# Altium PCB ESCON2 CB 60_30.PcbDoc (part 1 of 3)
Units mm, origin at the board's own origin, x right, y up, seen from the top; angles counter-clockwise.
Board outline 93.5 x 46 mm, 8 copper layers (Top Side, Inner Layer 1, Inner Layer 2, Inner Layer 3, Inner Layer 4, Inner Layer 5, Inner Layer 6, Bottom Side), stack 1.485 mm thick; 144 components, 77 nets, 473 pads, 3049 vias.
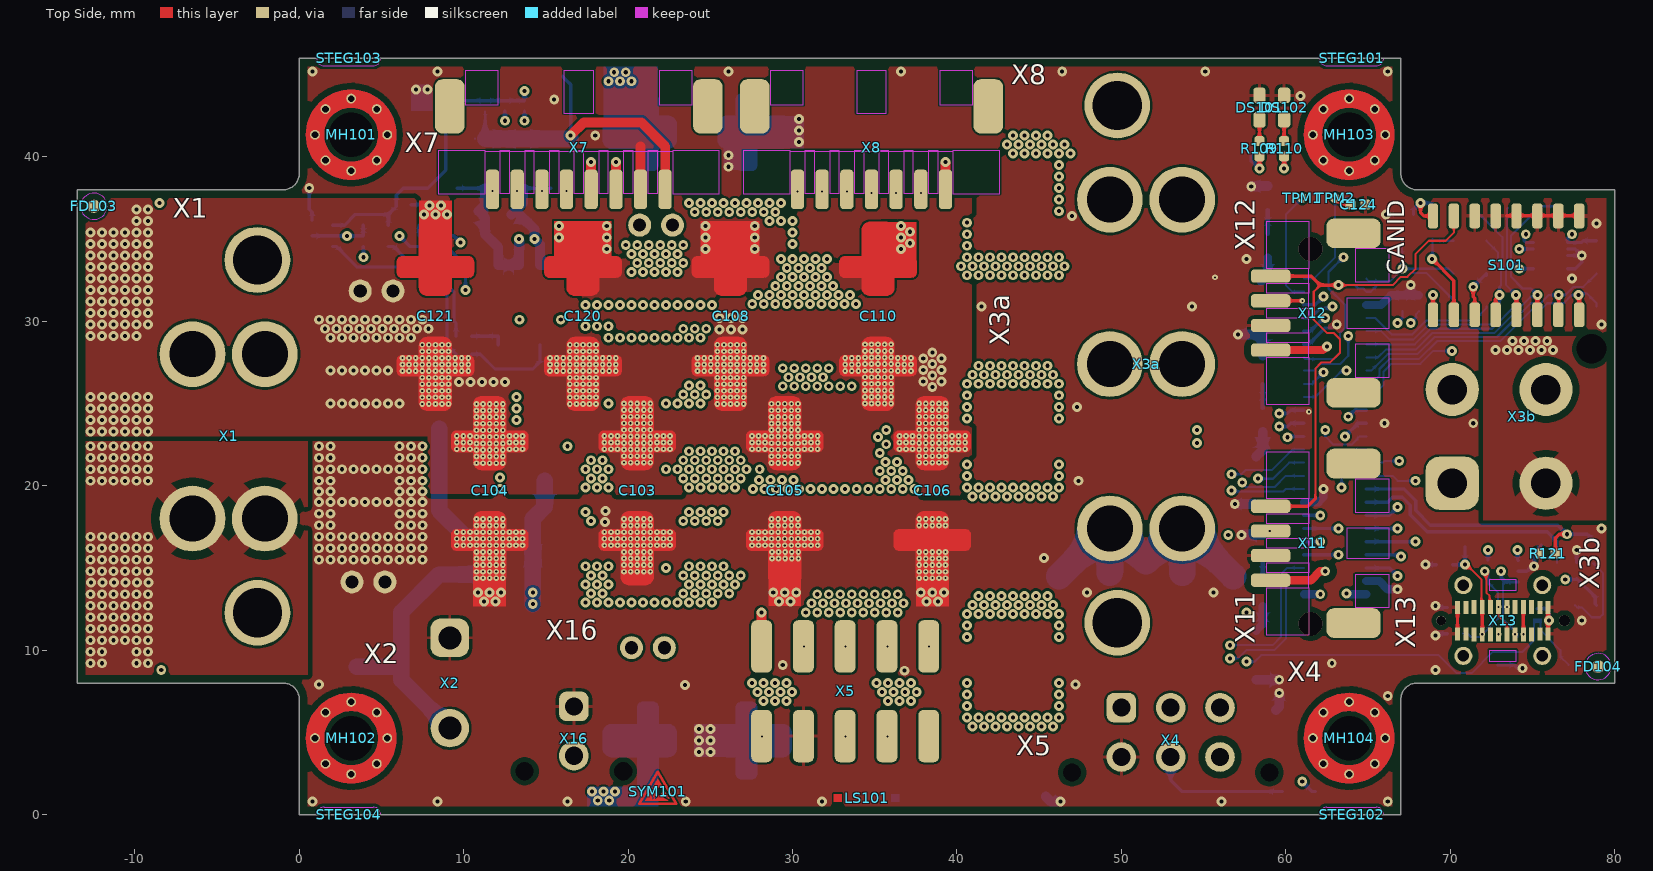
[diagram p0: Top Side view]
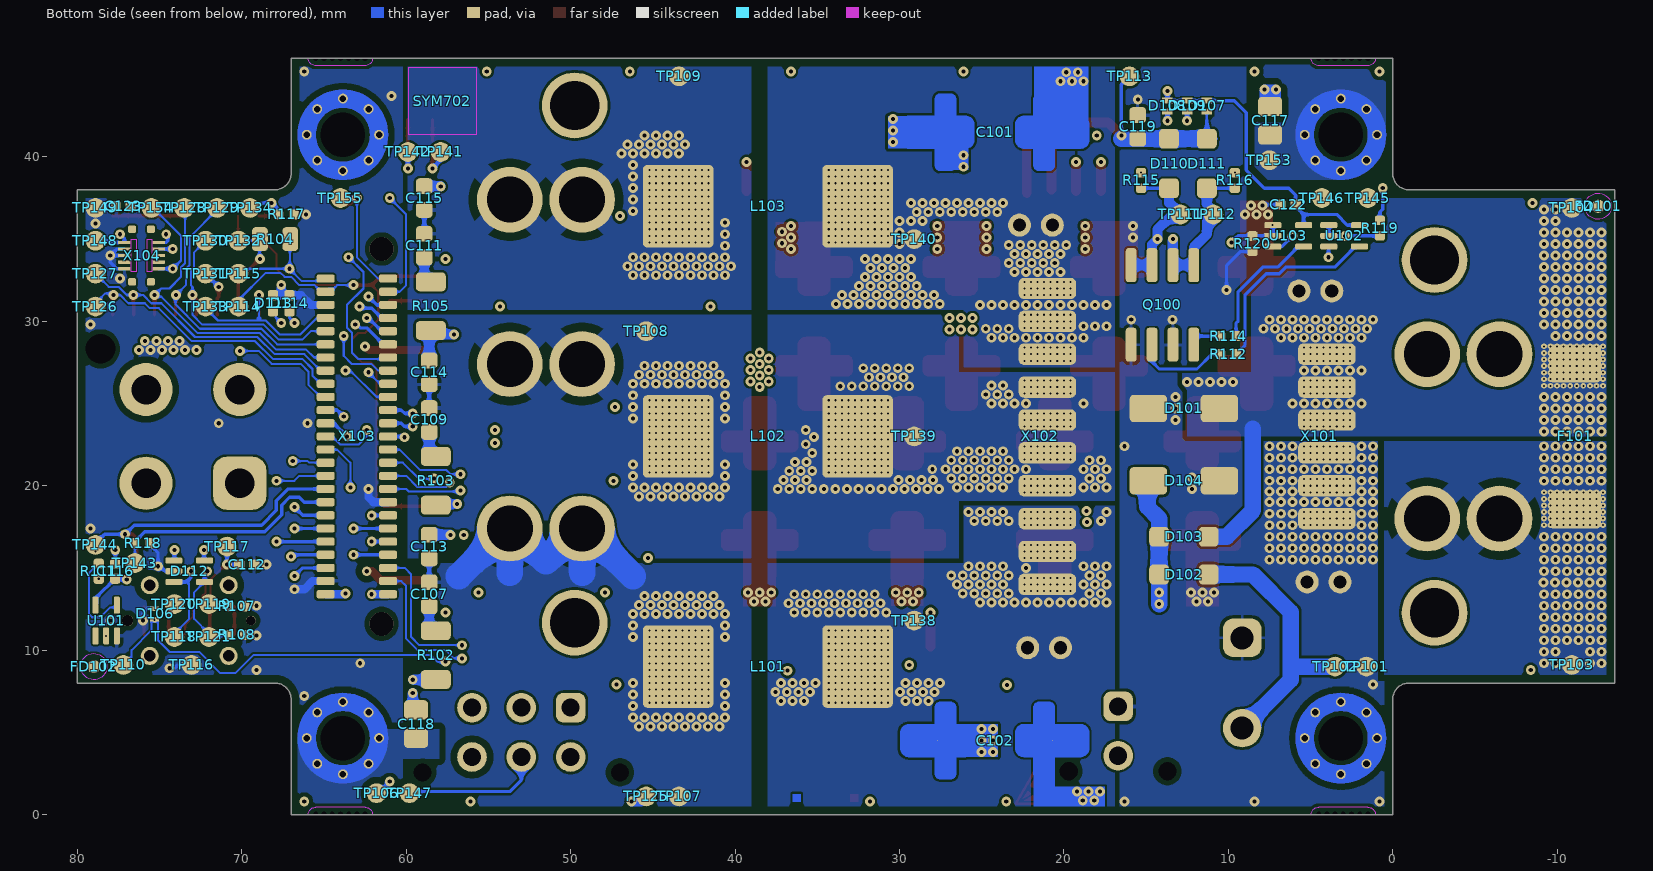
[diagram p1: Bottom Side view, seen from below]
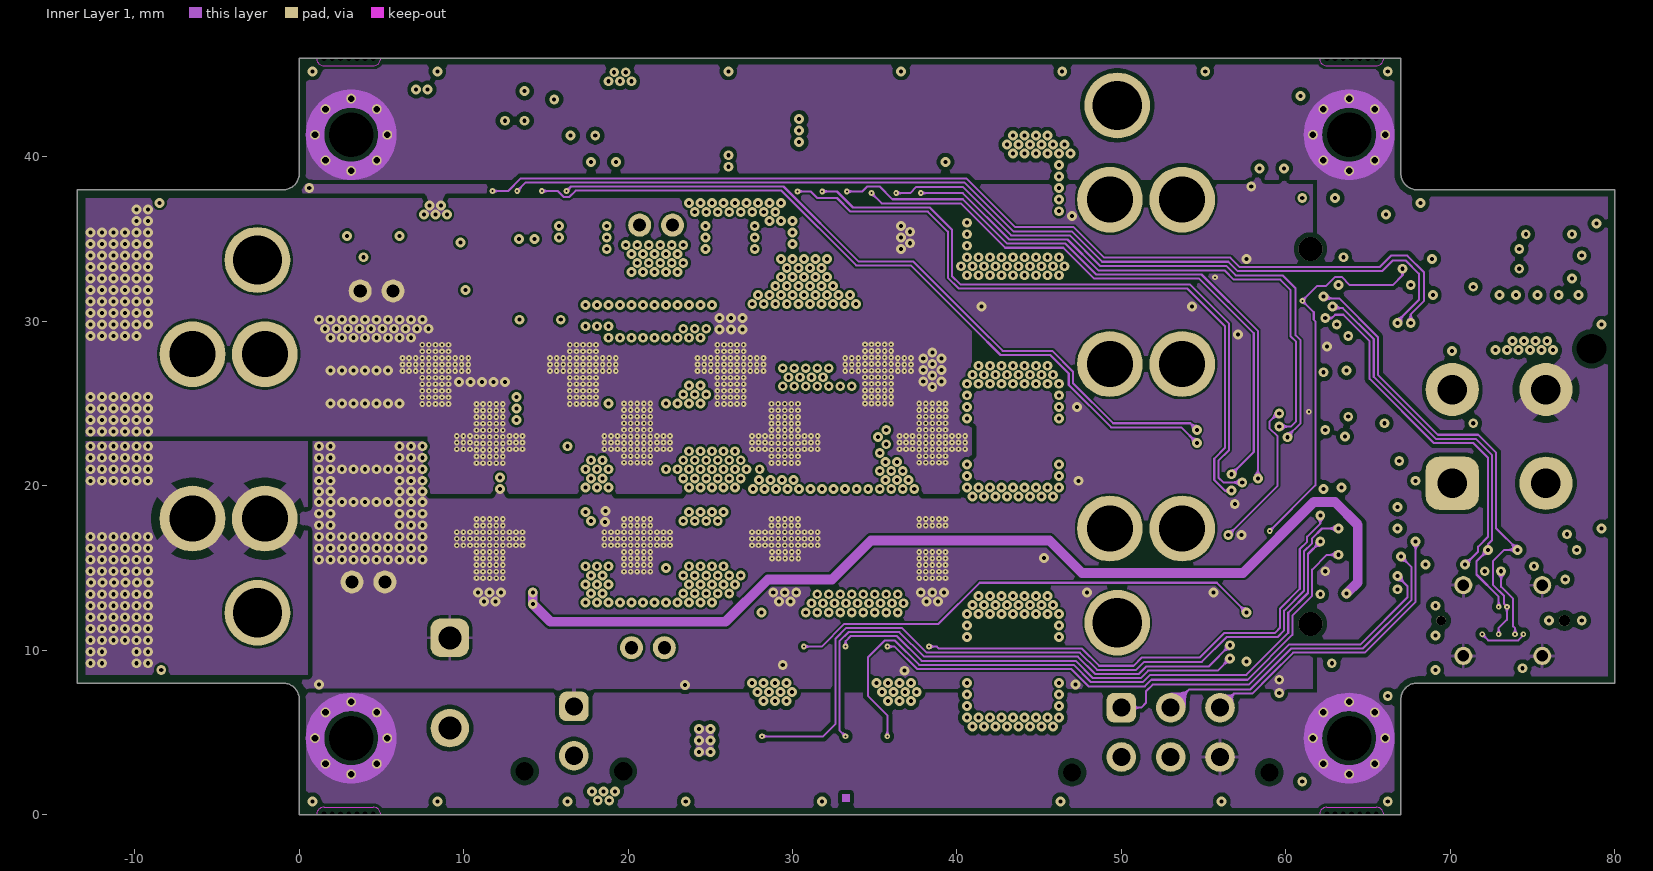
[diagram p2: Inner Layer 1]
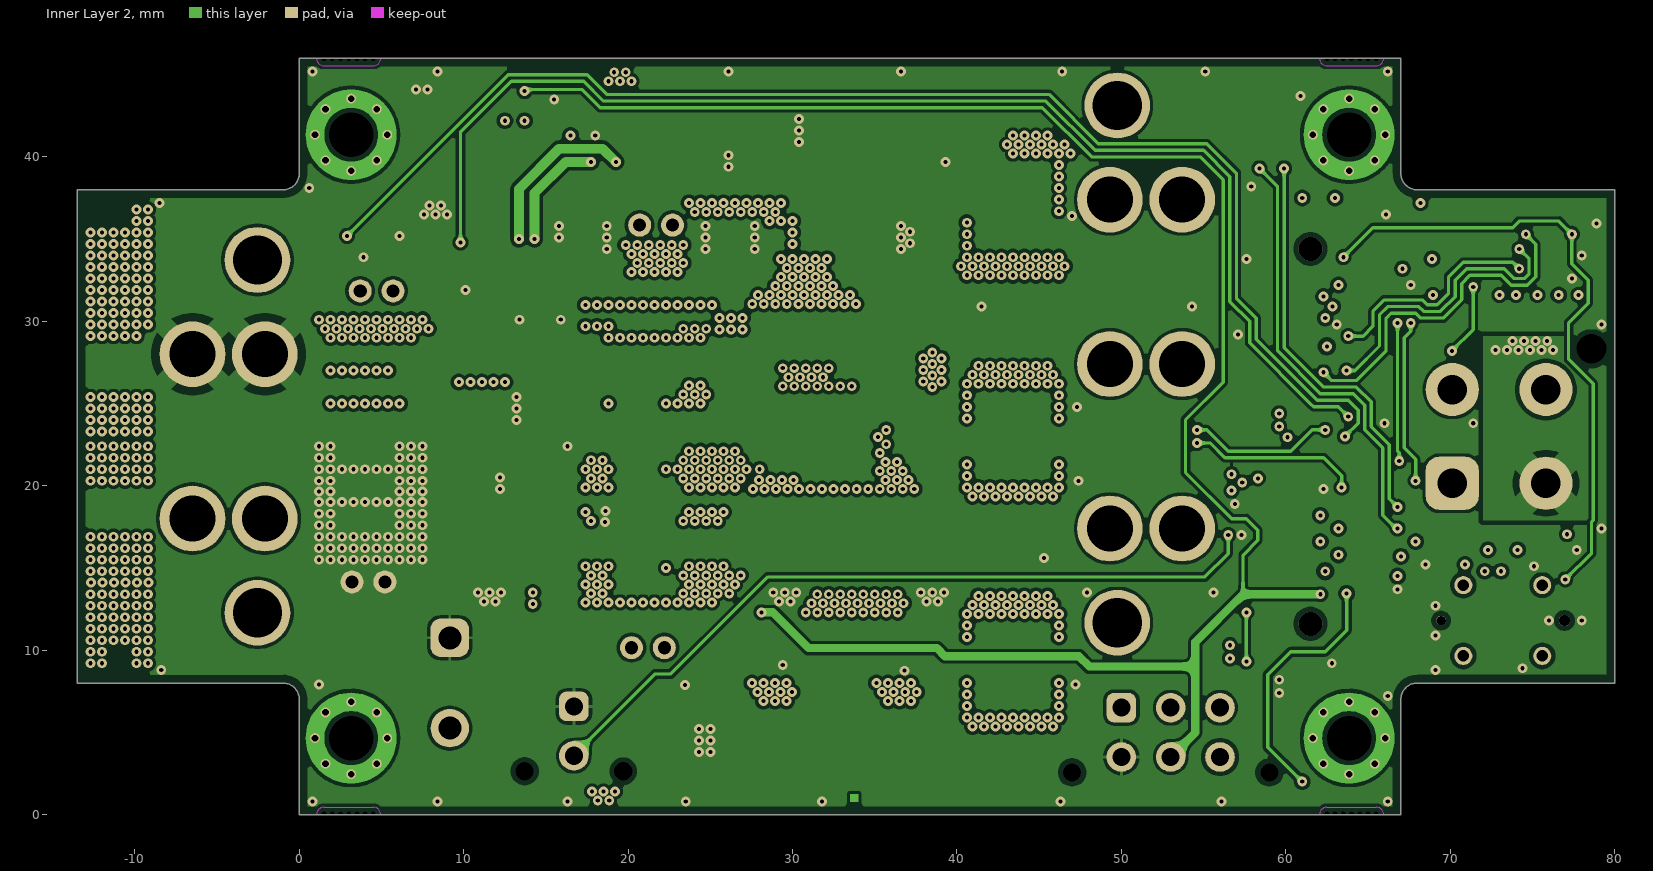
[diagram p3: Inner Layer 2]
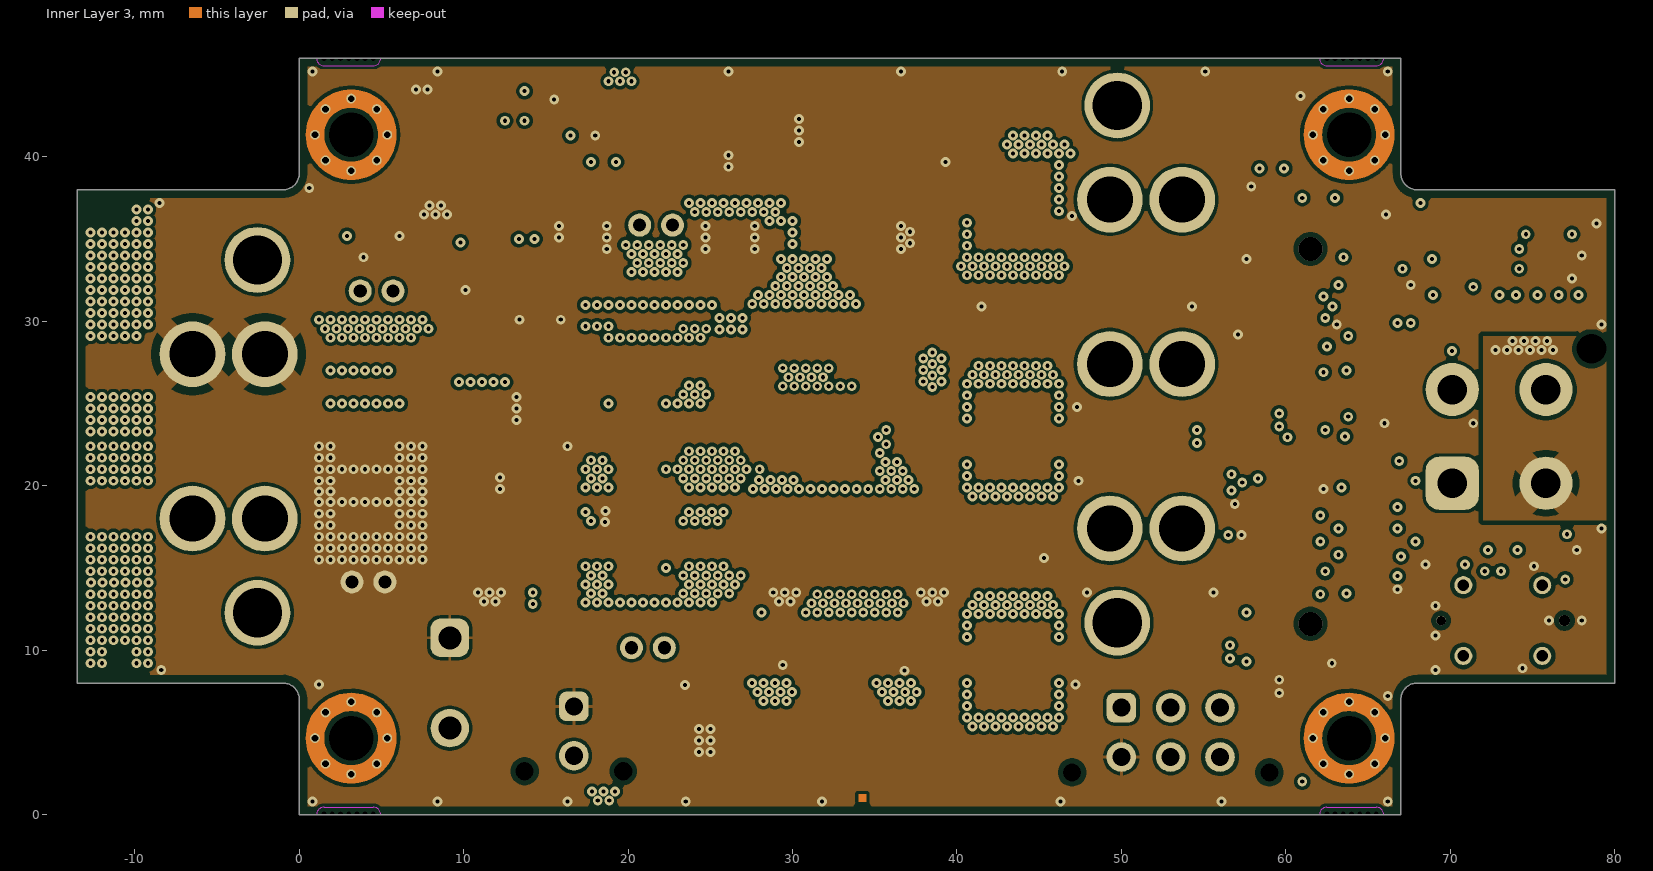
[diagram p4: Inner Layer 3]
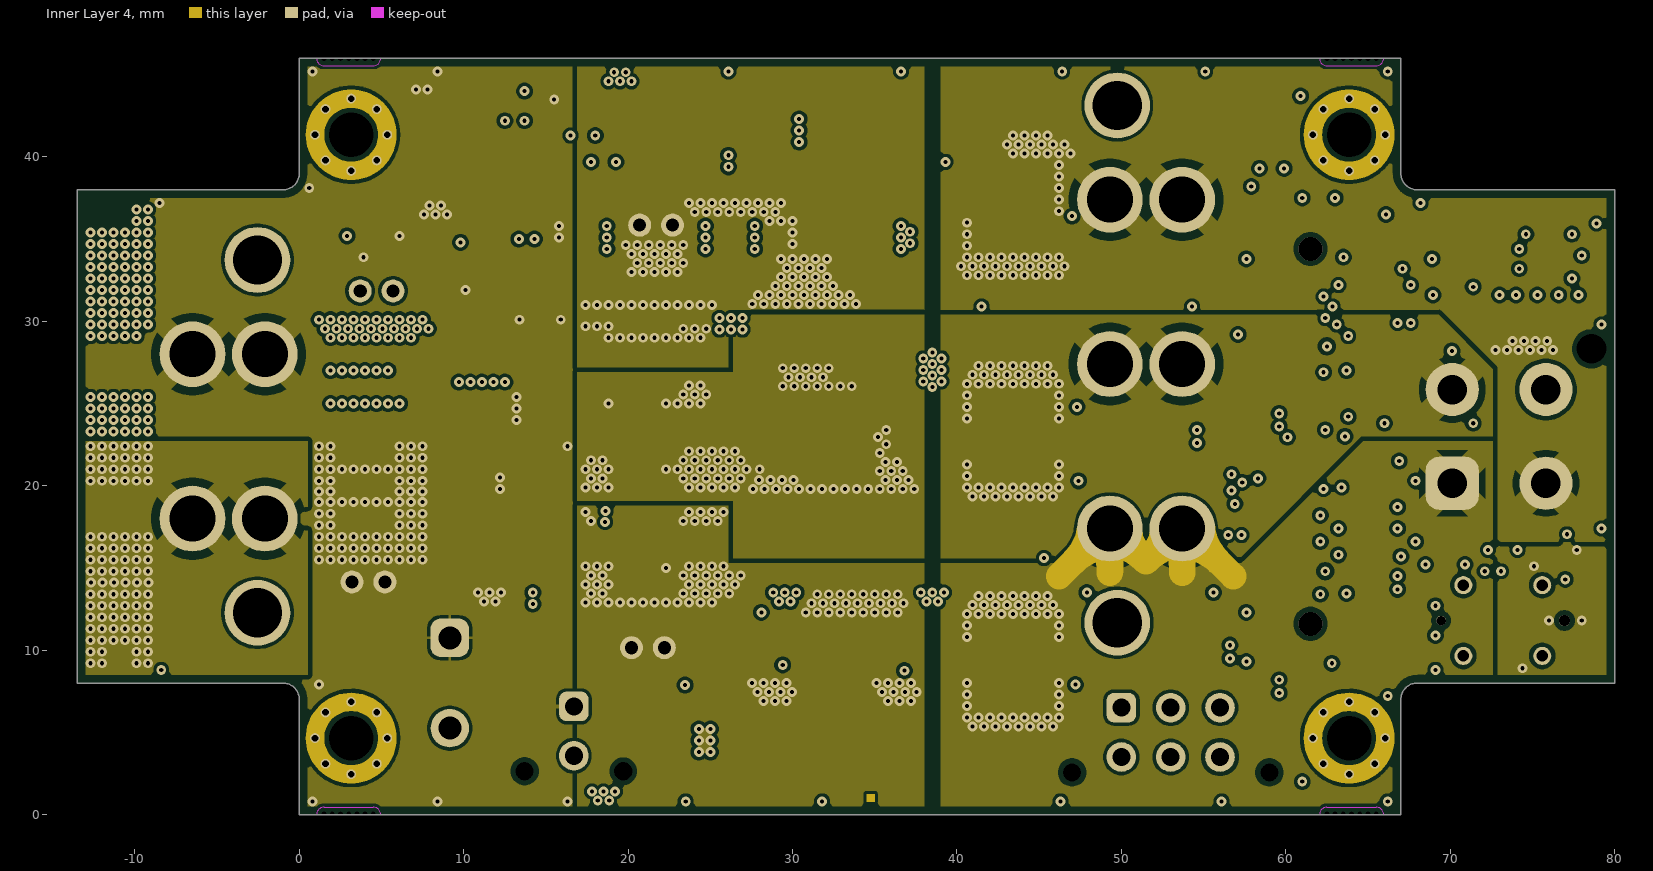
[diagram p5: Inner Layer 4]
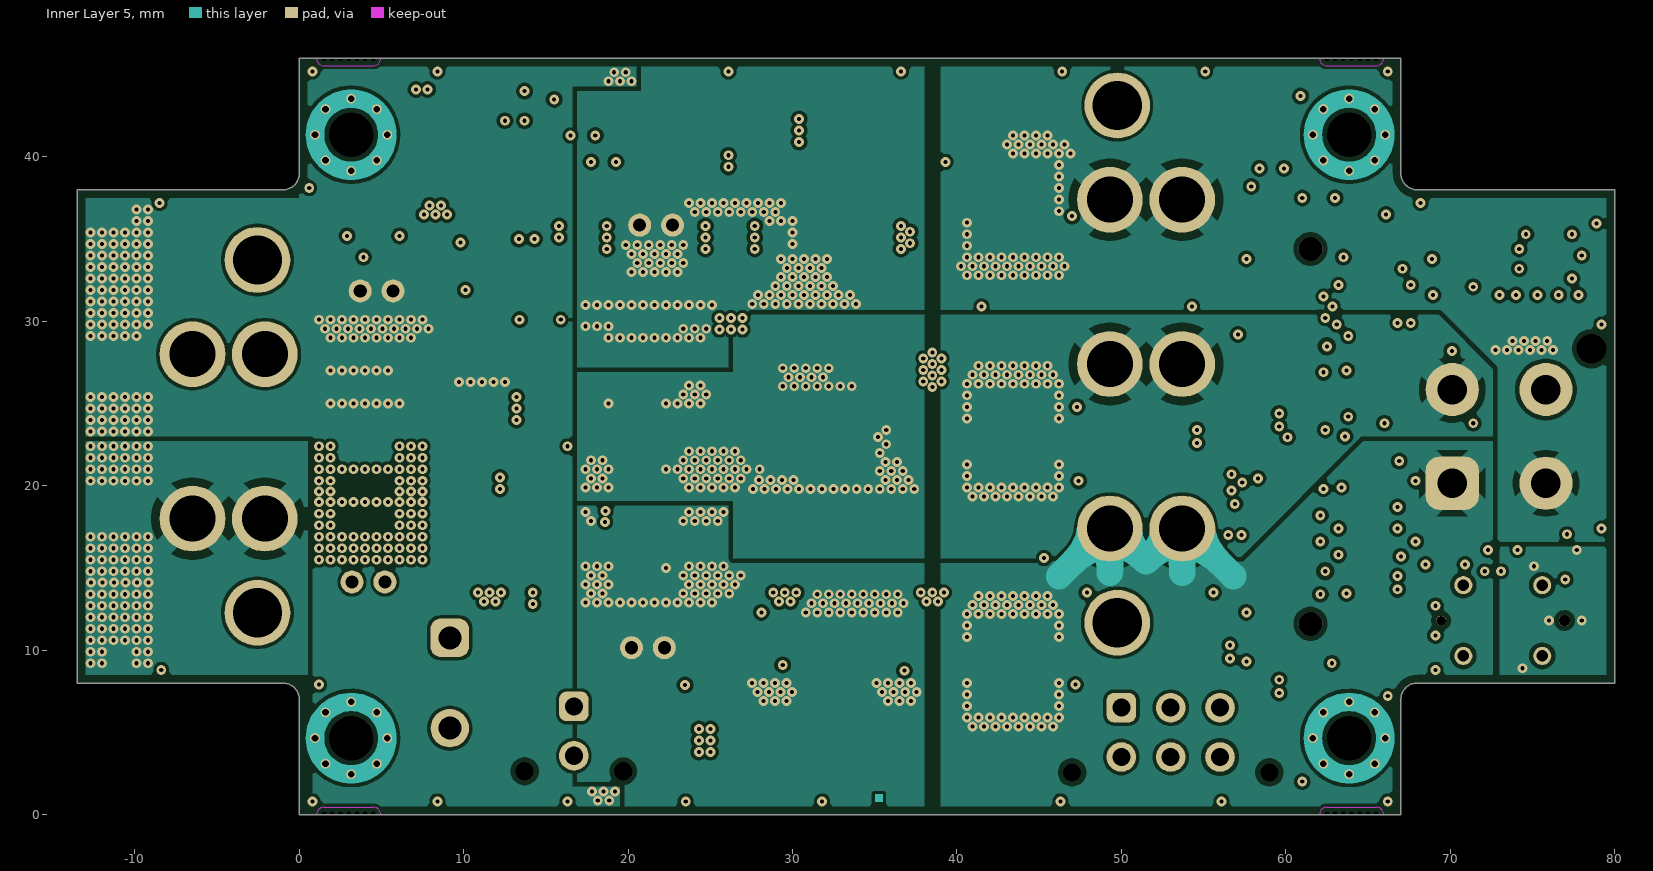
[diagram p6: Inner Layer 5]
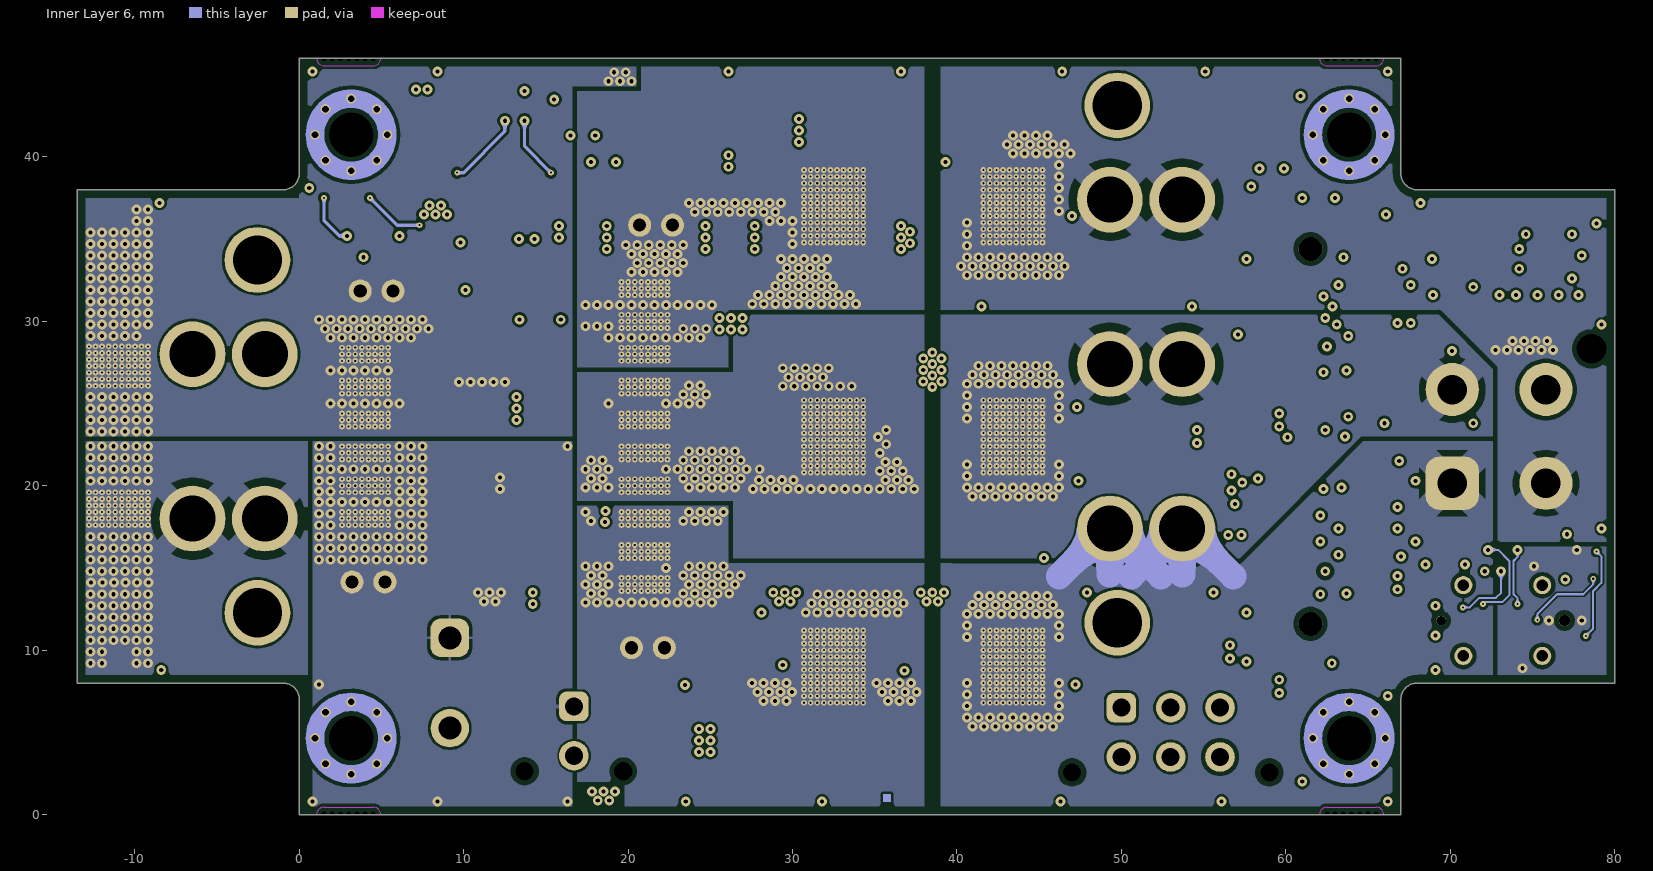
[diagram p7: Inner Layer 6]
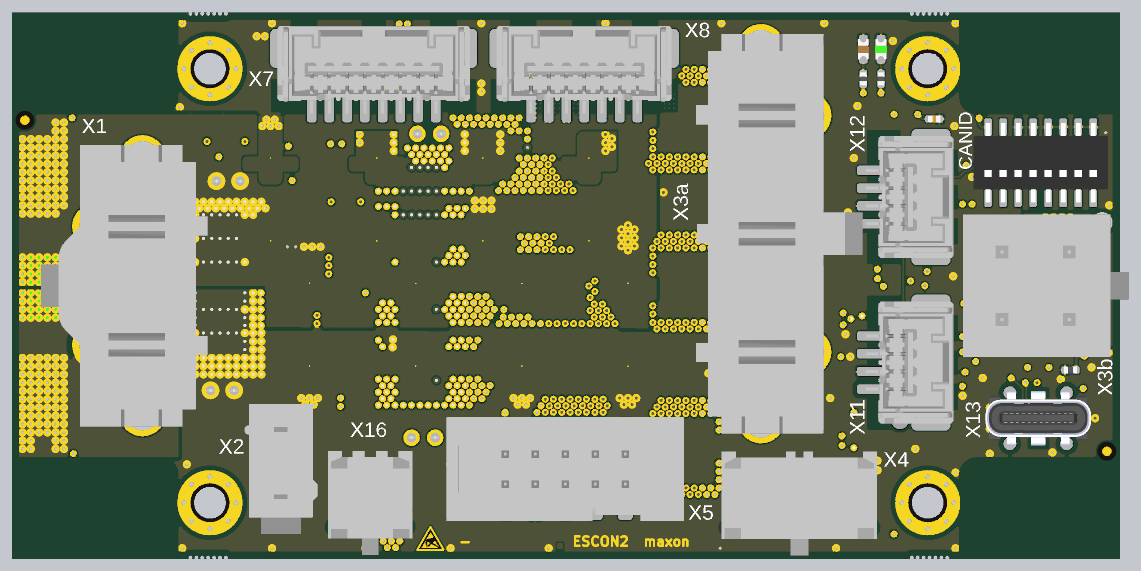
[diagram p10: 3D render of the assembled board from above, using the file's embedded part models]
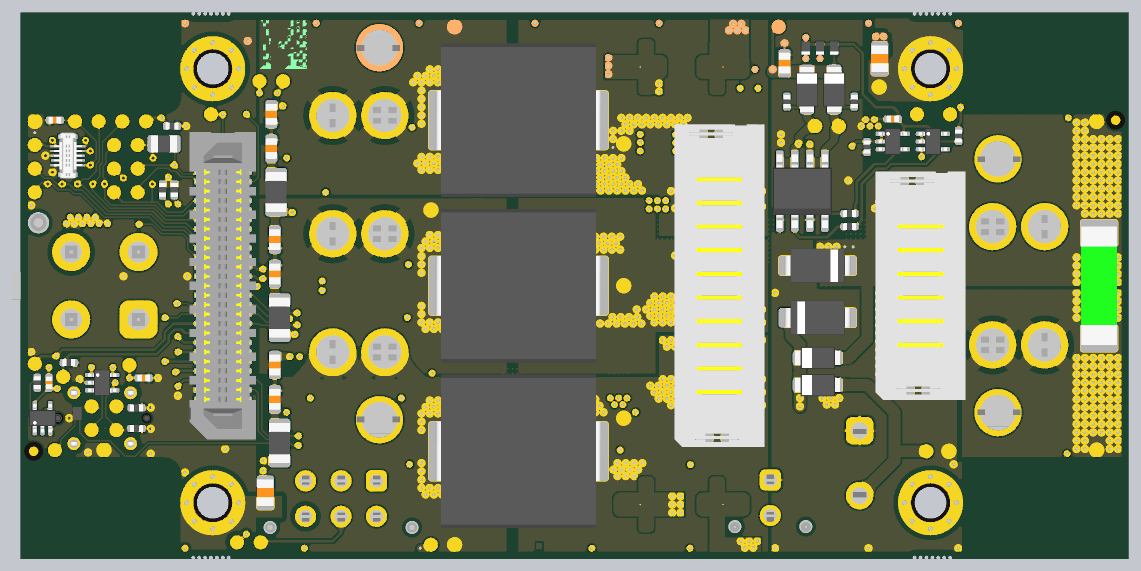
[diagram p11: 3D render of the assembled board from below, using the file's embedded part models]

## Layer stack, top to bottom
Top Solder: solder mask 0.015, Dk 3.5
Top Side: signal copper 0.03
Dielectric 1: prepreg 0.065, Dk 3.5
Inner Layer 1: signal copper 0.03
Dielectric 2: prepreg 0.125, Dk 3.7
Inner Layer 2: signal copper 0.035
Core 1: core 0.36, Dk 4.7
Inner Layer 3: signal copper 0.035
Dielectric 3: prepreg 0.125, Dk 3.7
Inner Layer 4: signal copper 0.035
Core 2: core 0.36, Dk 4.7
Inner Layer 5: signal copper 0.035
Dielectric 4: prepreg 0.125, Dk 3.7
Inner Layer 6: signal copper 0.03
Dielectric 5: prepreg 0.065, Dk 3.5
Bottom Side: signal copper 0.03
Bottom Solder: solder mask 0.015, Dk 3.5

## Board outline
0,7 ccw(c-1,7) -1,8 -13.5,8 -13.5,38 -1,38 ccw(c-1,39) 0,39 0,46 67,46 67,39 ccw(c68,39) 68,38 80,38 80,8 68,8 ccw(c68,7) 67,7 67,7.002 67,0 0,0

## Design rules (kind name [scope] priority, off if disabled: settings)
AssemblyTestPointUsage [All] p1: valid=2
AssemblyTestpoint [All] p1: testpointundercomponent=TRUE minsize=1 maxsize=2 preferedsize=1 minholesize=0 maxholesize=0 preferedholesize=0 testpointgrid=0.05 usegrid=TRUE gridoriginx=120 gridoriginy=100 gridtolerance=0 allowsidebottom=TRUE minspacing=1.9 padholecenterclearance=0.6
BoardOutlineClearance BOC_Overlay [OnLayer('Top Designator') OR OnLayer('Bottom Designator')] p1: gap=0 ignorepadtopadclearanceinfootprint=FALSE
BoardOutlineClearance BOC_Text [isText] p2: gap=0 ignorepadtopadclearanceinfootprint=FALSE
BoardOutlineClearance BOC_Fiducials [InComponent('FD*')] p3: gap=0.1 ignorepadtopadclearanceinfootprint=FALSE
BoardOutlineClearance BOC_Steg [InComponent('STEG*')] p4: gap=0 ignorepadtopadclearanceinfootprint=FALSE
BoardOutlineClearance BOC_Keepout [IsKeepout] p5: gap=0 ignorepadtopadclearanceinfootprint=FALSE
BoardOutlineClearance BC_SGND [InNet('SGND')] p6: gap=0.4 ignorepadtopadclearanceinfootprint=FALSE
BoardOutlineClearance BOC_All [All] p7: gap=0.5 ignorepadtopadclearanceinfootprint=FALSE
Clearance C_NPTH_All [(ObjectKind = 'Pad') And (Layer = 'MultiLayer') And (PadIsPlated = 'False') AND NOT HasFootprint('Steg_400X90_7Hole')AND HasFootprint('MTGNPH270A550V8H40')] p1: gap=0.3 ignorepadtopadclearanceinfootprint=TRUE except(0.298: THPad-Fill THPad-Poly THPad-Region Fill-Hole Poly-Hole Region-Hole)
Clearance SGND_Aussenlagen [InNet('SGND') vs OnLayer('Top Side') OR OnLayer('Bottom Side')] p2: gap=0.4 ignorepadtopadclearanceinfootprint=FALSE except(0: Track-Fill)
Clearance SGND_Innenlagen [InNet('SGND') vs OnLayer('Multi-Layer') OR OnMid] p3: gap=0.25 ignorepadtopadclearanceinfootprint=FALSE except(0.298: Region-Hole; 0.3: Arc-Hole Track-Hole SMDPad-Hole THPad-Hole Via-Hole Fill-Hole Poly-Hole Text-Hole)
Clearance C_PolygonPolygon [(InPolygon) vs (InPolygon)] p4: gap=0.3 ignorepadtopadclearanceinfootprint=FALSE
Clearance C_ClassHVtoAll_3 [InNetClass('HV') AND (ExistsOnLayer('Inner Layer 2') OR ExistsOnLayer('Inner Layer 3') OR ExistsOnLayer('Inner Layer 4') OR ExistsOnLayer('Inner Layer 5')) vs ExistsOnLayer('Inner Layer 2') OR ExistsOnLayer('Inner Layer 3') OR ExistsOnLayer('Inner Layer 4') OR ExistsOnLayer('Inner Layer 5')] p5: gap=0.2 ignorepadtopadclearanceinfootprint=FALSE except(0.3: Fill-Hole Poly-Hole Region-Hole)
Clearance C_ClassHVtoAll_2 [InNetClass('HV') AND ( ExistsOnLayer('Top Side') OR ExistsOnLayer('Bottom Side')) vs ExistsOnLayer('Top Side') OR ExistsOnLayer('Bottom Side')] p6: gap=0.15 ignorepadtopadclearanceinfootprint=FALSE except(0.3: Fill-Hole Poly-Hole Region-Hole)
Clearance C_ClassHVtoAll_1 [InNetClass('HV') AND ( ExistsOnLayer('Inner Layer 1') OR ExistsOnLayer('Inner Layer 6')) vs ExistsOnLayer('Inner Layer 1') OR ExistsOnLayer('Inner Layer 6')] p7: gap=0.15 ignorepadtopadclearanceinfootprint=FALSE except(0.3: Fill-Hole Poly-Hole Region-Hole)
Clearance C_ClassNVtoAll_2 [ExistsOnLayer('Inner Layer 2') OR ExistsOnLayer('Inner Layer 3') OR ExistsOnLayer('Inner Layer 4') OR ExistsOnLayer('Inner Layer 5') vs ExistsOnLayer('Inner Layer 2') OR ExistsOnLayer('Inner Layer 3') OR ExistsOnLayer('Inner Layer 4') OR ExistsOnLayer('Inner Layer 5')] p8: gap=0.2 ignorepadtopadclearanceinfootprint=FALSE except(0.3: Fill-Hole Poly-Hole Region-Hole)
Clearance C_ClassNVtoAll_1 [ExistsOnLayer('Top Side') OR ExistsOnLayer('Bottom Side') OR ExistsOnLayer('Inner Layer 1') OR ExistsOnLayer('Inner Layer 6') vs ExistsOnLayer('Top Side') OR ExistsOnLayer('Bottom Side') OR ExistsOnLayer('Inner Layer 1') OR ExistsOnLayer('Inner Layer 6')] p9: gap=0.125 ignorepadtopadclearanceinfootprint=FALSE except(0.3: Fill-Hole Poly-Hole Region-Hole)
Clearance C_PolygonAll [(InPolygon)] p10: gap=0.2 ignorepadtopadclearanceinfootprint=FALSE except(0.3: Arc-Hole Track-Hole SMDPad-Hole THPad-Hole Via-Hole Fill-Hole Poly-Hole Region-Hole Text-Hole)
Clearance C_STEGKeepout [InComponent('STEG*') vs IsKeepout] p11: gap=0 ignorepadtopadclearanceinfootprint=FALSE
Clearance C_All [All] p12: gap=0.15 ignorepadtopadclearanceinfootprint=FALSE except(0: SMDPad-Hole THPad-Hole Via-Hole Text-Hole; 0.298: Fill-Hole Poly-Hole Region-Hole)
ComponentClearance CC_Free3DBody [(ObjectKind = '3D Body') and not InComponent('*') vs (ObjectKind = '3D Body') and not InComponent('*')] p1: gap=0 collisioncheckmode=3 verticalgap=0 showdistances=FALSE
ComponentClearance CC_AllToAll [All] p2: gap=0.001 collisioncheckmode=3 verticalgap=0 showdistances=FALSE checkcomponentboundary=TRUE
DiffPairsRouting DPR_All [All] p1: maxlimit=0.3 minlimit=0.2 mostfreqgap=0.2 toplayer_minwidth=0.2 toplayer_maxwidth=0.25 toplayer_prefwidth=0.2 midlayer1_minwidth=0.2 midlayer1_maxwidth=0.25 midlayer1_prefwidth=0.2 midlayer2_minwidth=0.2 midlayer2_maxwidth=0.25 midlayer2_prefwidth=0.2 midlayer3_minwidth=0.2 midlayer3_maxwidth=0.25 midlayer3_prefwidth=0.2 midlayer4_minwidth=0.2 midlayer4_maxwidth=0.25 midlayer4_prefwidth=0.2 midlayer5_minwidth=0.2 midlayer5_maxwidth=0.25 midlayer5_prefwidth=0.2 midlayer6_minwidth=0.2 midlayer6_maxwidth=0.25 midlayer6_prefwidth=0.2 bottomlayer_minwidth=0.2 bottomlayer_maxwidth=0.25 bottomlayer_prefwidth=0.2 maxuncoupledlength=12.7
FabricationTestPointUsage [All] p1: valid=2 allowmultiple=FALSE
FabricationTestpoint [All] p1: side=3 testpointundercomponent=TRUE minsize=0.1 maxsize=10 preferedsize=1 minholesize=0 maxholesize=10 preferedholesize=1 testpointgrid=0.025 allowsidetop=TRUE allowsidebottom=TRUE usegrid=FALSE gridtolerance=0
HoleSize HS_All [All] p1: absolutevalues=TRUE maxlimit=5 minlimit=0.125 maxpercent=80.000 minpercent=20.000
HoleToHoleClearance HtHC_MicroToMicro [IsMicroVia vs IsMicroVia] p1: gap=0.2 allowstackedmicrovias=TRUE
HoleToHoleClearance HtHC_MicroToBuried [IsMicroVia vs isBuriedVia] p2: gap=0.225 allowstackedmicrovias=FALSE
HoleToHoleClearance HtHC_ThruToBuried [IsThruVia vs isBuriedVia] p3: gap=0.4 allowstackedmicrovias=TRUE
HoleToHoleClearance HtHC_STEG [InComponent('STEG*') vs InComponent('STEG*')] p4: gap=0.1 allowstackedmicrovias=TRUE
HoleToHoleClearance HtHC_All [All] p5: gap=0.4 allowstackedmicrovias=TRUE
LayerPairs LP_All [All] p1: enforce=TRUE
MinimumSolderMaskSliver MSMS_All [All] p1: minsoldermaskwidth=0.099
NetAntennae NA_All [All] p1: netantennaetolerance=0
PasteMaskExpansion PME_All [All] p1: expansion=0
PolygonConnect PCS_KerC [InComponent('C117')  OR InComponent('C118')] p1: connectstyle=Direct reliefconductorwidth=0.254 reliefentries=4 polygonreliefangle="90 Angle" airgapwidth=0.254
PolygonConnect PCS_X17 [InComponent('X17')] p2: connectstyle=Relief reliefconductorwidth=0.254 reliefentries=4 polygonreliefangle="45 Angle" airgapwidth=0.254
PolygonConnect PCS_TVS [InComponent('D101')   OR InComponent('D104')] p3: connectstyle=Direct reliefconductorwidth=0.254 reliefentries=4 polygonreliefangle="90 Angle" airgapwidth=0.254
PolygonConnect PCS_X3b [HasFootprint('MOLEX_1720650204')] p4: connectstyle=Relief reliefconductorwidth=1.5 reliefentries=4 polygonreliefangle="45 Angle" airgapwidth=0.4
PolygonConnect PCS_Power_THT [HasFootprint('MOLEX_428192214') OR HasFootprint('MOLEX_428193214')] p5: connectstyle=Relief reliefconductorwidth=1.2 reliefentries=4 polygonreliefangle="45 Angle" airgapwidth=0.5
PolygonConnect PCS_PowerPath_Direct [HasFootprint ('SAMTEC_UMPT-06-07.5-L-V-S-W')  OR HasFootprint('SAMTEC_UMPT-10-07.5-L-V-S-W')  OR HasFootprint('INDM1335X1260X500L275X470N')  OR HasFootprint('PANASONIC_F_VIB')  OR HasFootprint('FUSC1008X305X305L170N')] p6: connectstyle=Direct reliefconductorwidth=0.254 reliefentries=4 polygonreliefangle="90 Angle" airgapwidth=0.254
PolygonConnect PCS_Testpoint [Testpoint] p7: connectstyle=Direct reliefconductorwidth=0.254 reliefentries=4 polygonreliefangle="90 Angle" airgapwidth=0.254
PolygonConnect PCS_MountingHole [(InComponent('MH*'))] p8: connectstyle=Direct reliefconductorwidth=0.254 reliefentries=4 polygonreliefangle="90 Angle" airgapwidth=0.254
PolygonConnect PCS_DefaultComponents [InComponent('*')] p9: connectstyle=Relief reliefconductorwidth=0.2 reliefentries=4 polygonreliefangle="90 Angle" airgapwidth=0.2
PolygonConnect PCS_All [All] p10: connectstyle=Direct reliefconductorwidth=0.254 reliefentries=4 polygonreliefangle="90 Angle" airgapwidth=0.254
RoutingLayers RL_All [All] p1: top layer_v5=TRUE mid layer 1_v5=TRUE mid layer 2_v5=TRUE mid layer 3_v5=TRUE mid layer 4_v5=TRUE mid layer 5_v5=TRUE mid layer 6_v5=TRUE bottom layer_v5=TRUE
RoutingTopology RT_All [All] p1: topology=Shortest
RoutingVias RVS_MicroVia [IsMicroVia] p1: holewidth=0.125 width=0.35 viastyle="Through Hole" minholewidth=0.125 minwidth=0.35 maxholewidth=0.125 maxwidth=0.35
RoutingVias RVS_SkipVia [IsSkipVia] p2: holewidth=2 width=2 viastyle="Through Hole" minholewidth=2 minwidth=2 maxholewidth=2 maxwidth=2
RoutingVias RVS_BlindVia [IsBlindVia] p3: holewidth=2 width=2 viastyle="Through Hole" minholewidth=2 minwidth=2 maxholewidth=2 maxwidth=2
RoutingVias RVS_BuriedVia [IsBuriedVia] p4: holewidth=2 width=2 viastyle="Through Hole" minholewidth=2 minwidth=2 maxholewidth=2 maxwidth=2
RoutingVias RVS_ThruVia [IsThruVia] p5: holewidth=0.25 width=0.6 viastyle="Through Hole" minholewidth=0.25 minwidth=0.6 maxholewidth=0.25 maxwidth=0.6
SMDEntry SE_All [All] p1: side=TRUE corner=TRUE anyangle=TRUE
ShortCircuit S-C_All [All] p1: allowed=FALSE
SilkToSilkClearance StSC_All [All] p1: silktosilkclearance=0.25
SilkToSolderMaskClearance StSMC_Pad [IsPad] p1: minsilkscreentomaskgap=0.25 clearancetoexposedcopper=TRUE
SolderMaskExpansion SME_MicroVia [IsMicroVia] p1: expansion=0 istentingtop=TRUE soldermaskfromhole=TRUE
SolderMaskExpansion SME_BlindVia [IsBlindVia] p2: expansion=0 istentingtop=TRUE soldermaskfromhole=TRUE
SolderMaskExpansion SME_ThruVia [IsThruVia] p3: expansion=0.1 istentingtop=FALSE soldermaskfromhole=TRUE
SolderMaskExpansion SME_Check [All] p4 off: expansion=0.05 istentingtop=FALSE
SolderMaskExpansion SME_All [All] p5: expansion=0 istentingtop=FALSE
UnRoutedNet URN_All [All] p1: checkbadconnections=TRUE
UnpouredPolygon MP_All [All] p1:
Width W_All [All] p1: maxlimit=4 minlimit=0.125 preferedwidth=0.2 toplayer_prefwidth=0.125 midlayer1_prefwidth=0.125 midlayer2_minwidth=0.2 midlayer3_minwidth=0.2 midlayer4_prefwidth=0.125 midlayer5_minwidth=0.2 midlayer6_minwidth=0.2 bottomlayer_prefwidth=0.125 minimp=50.000000 maximp=50.000000 favimp=50.000000 checkconnectedcopper=TRUE
11 further rules are at their usual default settings.

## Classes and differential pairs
net class HV: C_VDigIO C_VL C_VP C_W1 C_W2 C_W3 NetC107_1 NetC109_1 NetC111_1 U V VL VP W

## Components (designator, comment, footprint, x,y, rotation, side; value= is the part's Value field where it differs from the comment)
C101 "EEHZA1K220P" PANASONIC_F_VIB 24.2,41.5 r0 bottom locked value=22µF
C102 "EEHZA1K220P" PANASONIC_F_VIB 24.2,4.5 r0 bottom locked value=22µF
C103 "EEHZA1K220P" PANASONIC_F_VIB 20.55,19.7 r270 top locked value=22µF
C104 "EEHZA1K220P" PANASONIC_F_VIB 11.575,19.7 r270 top locked value=22µF
C105 "EEHZA1K220P" PANASONIC_F_VIB 29.525,19.7 r270 top locked value=22µF
C106 "EEHZA1K220P" PANASONIC_F_VIB 38.5,19.7 r270 top locked value=22µF
C107 "0603 470p" CAPC160X80X100L35N 58.6,13.4 r90 bottom value=470pF
C108 "EEHZA1K220P" PANASONIC_F_VIB 26.225,30.3 r90 top locked value=22µF
C109 "0603 470p" CAPC160X80X100L35N 58.6,24 r90 bottom value=470pF
C110 "EEHZA1K220P" PANASONIC_F_VIB 35.2,30.3 r90 top locked value=22µF
C111 "0603 470p" CAPC160X80X100L35N 58.9,34.6 r90 bottom value=470pF
C112 "0402 100nF" CAPC100X50X70L25N 69.7,15.2 r0 bottom value=100nF
C113 "0603 220pF" CAPC160X80X100L35N 58.6,16.3 r270 bottom value=220pF
C114 "0603 220pF" CAPC160X80X100L35N 58.6,26.9 r270 bottom value=220pF
C115 "0603 220pF" CAPC160X80X100L35N 58.9,37.5 r270 bottom value=220pF
C116 "0402 100nF" CAPC100X50X70L25N 77.7,14.8 r270 bottom value=100nF
C117 "C0805C103KBRACAUTO" CAPC200X125X150L47N 7.45,42.2 r270 bottom value=10nF
C118 "C0805C103KBRACAUTO" CAPC200X125X150L47N 59.4,5.5 r270 bottom value=10nF
C119 "0603 100nF" CAPC160X80X100L35N 15.5,41.825 r270 bottom value=100nF
C120 "EEHZA1K220P" PANASONIC_F_VIB 17.25,30.3 r90 top locked value=22µF
C121 "EEHZA1K220P" PANASONIC_F_VIB 8.275,30.3 r90 top locked value=22µF
C122 "0402 100nF" CAPC100X50X70L25N 6.35,37.1 r180 bottom value=100nF
C123 "0402 100nF" CAPC100X50X70L25N 77.2,37 r180 bottom value=100nF
C124 "0402 100nF" CAPC100X50X70L25N 64.4,37.1 r180 top value=100nF
D101 "SMAJ60A" DIOM519X260X262L114X145N 12.7,24.7 r0 bottom
D102 "SS110LW" SODFL359X170X143L65X95N 12.7,14.6 r180 bottom
D103 "SS110LW" SODFL359X170X143L65X95N 12.7,16.9 r180 bottom
D104 "SMAJ60A" DIOM519X260X262L114X145N 12.7,20.3 r180 bottom
D106 "D12V0L1B2LP-7B" DIONPDFN2_102X60X60L25X50N 75.3,12.2 r270 bottom
D107 "1N4148WL2-TP" DIODFN2_102X60X60L25X50N 11.3,43.1 r90 bottom
D108 "1N4148WL2-TP" DIODFN2_102X60X60L25X50N 13.7,43.1 r90 bottom
D109 "1N4148WL2-TP" DIODFN2_102X60X60L25X50N 12.5,43.1 r90 bottom
D110 "SS110LW" SODFL359X170X143L65X95N 13.6,39.6 r270 bottom
D111 "SS110LW" SODFL359X170X143L65X95N 11.3,39.6 r270 bottom
D112 "PESD5V0L4UG" SOT23-5P65_210X110L28X20N 73.2,14.8 r270 bottom locked
D113 "EZAEG2A50AX" DIONPC105X53X43L26N 68.1,31.1 r270 bottom
D114 "EZAEG2A50AX" DIONPC105X53X43L26N 67.1,31.1 r270 bottom
DS101 "598-8010-107F" LEDSC80X160X90L45N_RED 58.4,43 r270 top
DS102 "598-8070-107F" LEDSC80X160X90L45N_GREEN 59.9,43 r270 top
F101 "0678H9400-02" FUSC1008X305X305L170N -11.1,23 r90 bottom locked
FD101 "FDc80c160" FIDUCIAL_c80_c160 -12.5,37 r180 bottom
FD102 "FDc80c160" FIDUCIAL_c80_c160 79,9 r180 bottom
FD103 "FDc80c160" FIDUCIAL_c80_c160 -12.5,37 r0 top locked
FD104 "FDc80c160" FIDUCIAL_c80_c160 79,9 r0 top
L101 "SRP1245A-R47M" INDM1335X1260X500L275X470N 38,9 r180 bottom value=470nH
L102 "SRP1245A-R47M" INDM1335X1260X500L275X470N 38,23 r180 bottom value=470nH
L103 "SRP1245A-R47M" INDM1335X1260X500L275X470N 38,37 r180 bottom value=470nH
LS101 "LAYERSTAIR 8 LAYER" 8LS400X50w/oLETTERS_KEEPOUT 34.5,1 r0 top locked
MH101 "MTGNPH270A550V8H40" MTGNPH270A550V8H40 3.15,41.35 r0 top locked
MH102 "MTGNPH270A550V8H40" MTGNPH270A550V8H40 3.15,4.65 r0 top locked
MH103 "MTGNPH270A550V8H40" MTGNPH270A550V8H40 63.85,41.35 r0 top locked
MH104 "MTGNPH270A550V8H40" MTGNPH270A550V8H40 63.85,4.65 r0 top locked
Q100 "VNS1NV04DP-E" SOIC8P127_490X599X175L83X41N 14,31 r180 bottom
R102 "1206 47R" RESC320X160X90L47N 58.2,9.7 r90 bottom value=47
R103 "1206 47R" RESC320X160X90L47N 58.2,20.3 r90 bottom value=47
R104 "0805 120R" RESC200X125X84L35N 67.975,35 r180 bottom value=120
R105 "1206 47R" RESC320X160X90L47N 58.5,30.92 r90 bottom value=47
R107 "0402 5.1k" RESC100X52X40L22N 70.3,12.675 r180 bottom value=5.1k
R108 "0402 5.1k" RESC100X52X40L22N 70.3,10.925 r180 bottom value=5.1k
R109 "0402 680R" RESC100X52X40L22N 58.4,40.5 r90 top value=680
R110 "0402 680R" RESC100X52X40L22N 59.9,40.5 r90 top value=680
R111 "0402 47R" RESC100X52X40L22N 78.7,14.8 r90 bottom value=47
R112 "0402 220R" RESC100X52X40L22N 10,28 r0 bottom value=220
R114 "0402 220R" RESC100X52X40L22N 10,29.1 r0 bottom value=220
R115 "0402 2.2k" RESC100X52X40L22N 15.3,38.57 r90 bottom value=2.2k
R116 "0402 2.2k" RESC100X52X40L22N 9.6,38.57 r90 bottom value=2.2k
R117 "0402 0" RESC100X52X40L22N 67.3,36.5 r0 bottom value=0
R118 "0402 10k" RESC100X52X40L22N 76.03,16.5 r0 bottom value=10k
R119 "0402 10k" RESC100X52X40L22N 0.775,35.67 r270 bottom value=10k
R120 "0402 10k" RESC100X52X40L22N 8.525,34.725 r90 bottom value=10k
R121 "0402 10k" RESC100X52X40L22N 75.925,15.875 r0 top value=10k
S101 "DHN-08F-T-V" SOIC16P127_1139X671X151L61X41N 73.4,33.4 r180 top locked
STEG101 "Steg400X90_7Hole" Steg_400X90_7Hole 64,46 r180 top
STEG102 "Steg400X90_7Hole" Steg_400X90_7Hole 64,0 r0 top
STEG103 "Steg400X90_7Hole" Steg_400X90_7Hole 3,46 r180 top
STEG104 "Steg400X90_7Hole" Steg_400X90_7Hole 3,0 r0 top
SYM101 "ESD250X225" ESD_copper_X-small 21.8,1.4 r0 top
SYM702 "BARCODE_EMS410x410" BARCODE_EMS_410x410 57.8,43.4 r180 bottom
TP101 "TPc120" TESTPOINT_c120 1.6,9 r180 bottom locked
TP102 "TPc120" TESTPOINT_c120 3.5,9 r180 bottom locked
TP103 "TPc120" TESTPOINT_c120 -10.9,9.1 r180 bottom locked
TP104 "TPc120" TESTPOINT_c120 -10.9,36.9 r180 bottom locked
TP106 "TPc120" TESTPOINT_c120 61.8,1.3 r180 bottom locked
TP107 "TPc120" TESTPOINT_c120 43.4,1.1 r180 bottom locked
TP108 "TPc120" TESTPOINT_c120 45.4,29.4 r180 bottom locked
TP109 "TPc120" TESTPOINT_c120 43.4,44.9 r180 bottom locked
TP110 "TPc120" TESTPOINT_c120 77.2,9.1 r180 bottom locked
TP111 "TPc120" TESTPOINT_c120 12.9,36.5 r180 bottom
TP112 "TPc120" TESTPOINT_c120 10.9,36.5 r180 bottom locked
TP113 "TPc120" TESTPOINT_c120 16,44.9 r180 bottom
TP114 "TPc120" TESTPOINT_c120 70.2,30.9 r180 bottom locked
TP115 "TPc120" TESTPOINT_c120 70.2,32.9 r180 bottom locked
TP116 "TPc120" TESTPOINT_c120 73.05,9.1 r180 bottom locked
TP117 "TPc120" TESTPOINT_c120 70.9,16.3 r180 bottom locked
TP118 "TPc120" TESTPOINT_c120 74.1,10.8 r180 bottom locked
TP119 "TPc120" TESTPOINT_c120 72,12.8 r180 bottom locked
TP120 "TPc120" TESTPOINT_c120 74.1,12.8 r180 bottom locked
TP121 "TPc120" TESTPOINT_c120 72,10.8 r180 bottom locked
TP125 "TPc120" TESTPOINT_c120 45.4,1.1 r180 bottom locked
TP126 "TPc120" TESTPOINT_c120 78.9,30.9 r180 bottom locked
TP127 "TPc120" TESTPOINT_c120 78.9,32.9 r180 bottom locked
TP128 "TPc120" TESTPOINT_c120 73.5,36.9 r180 bottom locked
TP129 "TPc120" TESTPOINT_c120 71.5,36.9 r180 bottom locked
TP130 "TPc120" TESTPOINT_c120 72.2,34.9 r180 bottom locked
TP131 "TPc120" TESTPOINT_c120 72.2,32.9 r180 bottom locked
TP132 "TPc120" TESTPOINT_c120 70.2,34.9 r180 bottom locked
TP133 "TPc120" TESTPOINT_c120 72.2,30.9 r180 bottom locked
TP134 "TPc120" TESTPOINT_c120 69.5,36.9 r180 bottom locked
TP138 "TPc120" TESTPOINT_c120 29.1,11.8 r180 bottom locked
TP139 "TPc120" TESTPOINT_c120 29.1,23 r180 bottom locked
TP140 "TPc120" TESTPOINT_c120 29.1,35 r180 bottom locked
TP141 "TPc120" TESTPOINT_c120 57.9,40.3 r180 bottom locked
TP142 "TPc120" TESTPOINT_c120 59.9,40.3 r180 bottom locked
TP143 "TPc120" TESTPOINT_c120 76.5,15.3 r180 bottom locked
TP144 "TPc120" TESTPOINT_c120 78.9,16.4 r180 bottom locked
TP145 "TPc120" TESTPOINT_c120 1.5,37.5 r180 bottom locked
TP146 "TPc120" TESTPOINT_c120 4.3,37.5 r180 bottom locked
TP147 "TPc120" TESTPOINT_c120 59.8,1.3 r180 bottom locked
TP148 "TPc120" TESTPOINT_c120 78.9,34.9 r180 bottom locked
TP149 "TPc120" TESTPOINT_c120 78.9,36.9 r180 bottom locked
TP153 "TPc120" TESTPOINT_c120 7.5,39.8 r180 bottom locked
TP154 "TPc120" TESTPOINT_c120 75.5,36.9 r0 bottom locked
TP155 "TPc120" TESTPOINT_c120 64,37.5 r0 bottom locked
TPM1 "TPMc50" TESTPOINTMEASURE_c50 61,37.5 r0 top
TPM2 "TPMc50" TESTPOINTMEASURE_c50 63,37.5 r0 top
U101 "SN74LVC1G17DCK" SOT23-5P65_210X110L28X20N 78.25,11.8 r180 bottom locked
U102 "SN74AHCT1G00DCKR" SOT23-5P65_210X110L28X20N 2.95,35.2 r270 bottom
U103 "SN74AHCT1G00DCKR" SOT23-5P65_210X110L28X20N 6.35,35.2 r270 bottom
X1 "428192214" MOLEX_428192214 -6.5,23 r90 top locked
X2 "39281023" MOLEX_39281023 9.15,8 r0 top locked
X3a "428193214" MOLEX_428193214 53.7,27.4 r270 top locked
X3b "1720650204" MOLEX_1720650204 72.975,23 r270 top locked
X4 "430450612" "MOLEX_ 430450612" 53,5 r180 top locked
X5 "52601-S10-8LF" AMPHENOL_52601-S10-8LF 33.2,7.5 r0 top locked
X7 "5025840860" MOLEX_5025840860 17,41.8 r0 top locked
X8 "5025840760" MOLEX_5025840760 34.8,41.8 r0 top
X11 "5025840460" MOLEX_5025840460 62.85,16.5 r270 top locked
X12 "5025840460" MOLEX_5025840460 62.85,30.5 r270 top locked
X13 "USB4115-03-C" GTC_USB4115-03-C 73.2,11.8 r180 top locked
X16 "430450212" "MOLEX_ 430450212" 16.7,5.075 r180 top locked
X101 "UMPT-06-07.5-L-V-S-W" SAMTEC_UMPT-06-07.5-L-V-S-W 4,23 r270 bottom locked
X102 "UMPT-10-07.5-L-V-S-W" SAMTEC_UMPT-10-07.5-L-V-S-W 21,23 r270 bottom locked
X103 "ERM8-025-08.0-L-DV" SAMTEC_ERM8-025-08.0-L-DV 63,23 r90 bottom locked
X104 "AXT410124" PANASONIC_AXT410124 76.1,34 r270 bottom

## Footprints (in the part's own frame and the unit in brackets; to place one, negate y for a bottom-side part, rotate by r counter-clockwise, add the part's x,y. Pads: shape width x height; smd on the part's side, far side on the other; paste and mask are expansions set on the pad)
8LS400X50w/oLETTERS_KEEPOUT [mm] "Layerstair 8 Layers, 4.00 mm X 0.5 mm, without Letters and KeepOut"
  Top Side region: -2,-0.25 -1.5,-0.25 -1.5,0.25 -2,0.25
  Inner Layer 1 region: -1.5,-0.25 -1,-0.25 -1,0.25 -1.5,0.25
  Inner Layer 2 region: -1,-0.25 -0.5,-0.25 -0.5,0.25 -1,0.25
  Inner Layer 3 region: -0.5,-0.25 0,-0.25 0,0.25 -0.5,0.25
  Inner Layer 6 region: 1.5,0.25 1,0.25 1,-0.25 1.5,-0.25
  Inner Layer 4 region: 0.5,0.25 0,0.25 0,-0.25 0.5,-0.25
  Inner Layer 5 region: 1,0.25 0.5,0.25 0.5,-0.25 1,-0.25
  Bottom Side region: 1.5,-0.25 2,-0.25 2,0.25 1.5,0.25
AMPHENOL_52601-S10-8LF [mm] "Header, 2.54mm Pitch, Dual Row, SMT, Vertical, 10 Circuits"
  rrect50% 1.27x3.18 smd: 1(-5.08,-2.73) 2(-5.08,2.73) 3(-2.54,-2.73) 4(-2.54,2.73) 5(0,-2.73) 6(0,2.73) 7(2.54,-2.73) 8(2.54,2.73) 9(5.08,-2.73) 10(5.08,2.73)
  body extent -10.05,-4.38 10.05,4.38, height 12.76
BARCODE_EMS_410x410 [mm] "Barcode EMS, 4.10 mm L X 4.10 mm W X 0.00 mm H body"
  Top Side keep-out region: -2.05,2.05 2.05,2.05 2.05,-2.05 -2.05,-2.05
  body extent -2.05,-2.05 2.05,2.05, height 0.01
CAPC100X50X70L25N [mm] "Capacitor, Chip; 1.00 mm L X 0.50 mm W X 0.70 mm H body"
  rrect49% 0.63x0.61 smd: 1(-0.45,0) 2(0.45,0)
  body extent -0.55,-0.3 0.55,0.3, height 0.7
CAPC160X80X100L35N [mm] "Capacitor, Chip; 1.60 mm L X 0.80 mm W X 1.00 mm H body"
  rrect50% 0.96x1.02 smd: 1(-0.725,0) 2(0.725,0)
  body extent -0.9,-0.5 0.9,0.5, height 1
CAPC200X125X150L47N [mm] "Capacitor, Chip; 2.00 mm L X 1.25 mm W X 1.50 mm H body"
  rrect42% 1.18x1.47 smd: 1(-0.865,0) 2(0.865,0)
  body extent -1.15,-0.72 1.15,0.72, height 1.5
DIODFN2_102X60X60L25X50N [mm] "Diode, Dual Flat No-Lead (DFN 2 Pin); 2 pin, 1.025 mm L X 0.60 mm W X 0.60 mm H body"
  rect 0.36x0.63 smd: 1(-0.325,0) 2(0.325,0)
  body extent -0.55,-0.35 0.55,0.35, height 0.6
DIOM519X260X262L114X145N [mm] "Diode, Molded Body; 4.295 mm L X 2.605 mm W X 2.62 mm H body"
  rrect30% 2.277x1.665 smd: 1(-2.16,0) 2(2.16,0)
  body extent -2.8,-1.46 2.8,1.46, height 2.62
DIONPC105X53X43L26N [mm] "Diode, Non-polarized, Chip; 1.05 mm L X 0.53 mm W X 0.43 mm H Body"
  rrect50% 0.65x0.625 smd: 1(-0.485,0) 2(0.485,0)
  body extent -0.6,-0.31 0.6,0.31, height 0.43
DIONPDFN2_102X60X60L25X50N [mm] "Diode, Non-polarized, Dual Flat No-Lead, 2 pin; 1.025 mm L X 0.60 mm W X 0.60 mm H body"
  rect 0.28x0.549 smd: 1(-0.325,0) 2(0.325,0)
  body extent -0.55,-0.35 0.55,0.35, height 0.6
ESD_copper_X-small [mm] "ESD-Sign copper 2.5x2.25mm"
  Top Side region: 1157 vertices and 0 holes, not listed, extent -0.761,-0.567 0.653,0.041
  Top Side region: 575 vertices and 0 holes, not listed, extent 0.2,-0.436 0.704,0.047
  Top Side region: 602 vertices and 0 holes, not listed, extent -0.347,0.129 0.256,0.767
  Top Side lines w0.15: -1.127,-0.747 -0.002,1.202 1.123,-0.747 -1.127,-0.747
FIDUCIAL_c80_c160 [mm] "Fiducial, Global; 0 pin"
  round 0.8 smd paste-0.8 mask+0.4: 1(0,0)
  Top Side keep-out circle w0.025: c0,0 r0.8
FUSC1008X305X305L170N [mm] "Fuse, Chip; 10.08 mm L X 3.05 mm W X 3.05 mm H Body"
  rrect22% 2.311x3.162 smd: 1(-4.44,0) 2(4.44,0)
  body extent -5.04,-1.53 5.04,1.53, height 3.05
GTC_USB4115-03-C [mm] "USB Type C, SHLD, 24poles"
  round 0.66 hole 0.66 unplated mask+0.15: 0(-3.75,0)
  round 0.58 hole 0.58 unplated mask+0.15: 0(3.75,0)
  rect 0.3x0.79 smd: A1(-2.75,0.805) A2(-2.25,0.805) A11(2.25,0.805) A12(2.75,0.805) B1(2.75,-0.805) B2(2.25,-0.805) B11(-2.25,-0.805) B12(-2.75,-0.805)
  rect 0.3x0.85 smd: A3(-1.75,0.835) A4(-1.25,0.835) A5(-0.75,0.835) A6(-0.25,0.835) A7(0.25,0.835) A8(0.75,0.835) A9(1.25,0.835) A10(1.75,0.835) B3(1.75,-0.835) B4(1.25,-0.835) B5(0.75,-0.835) B6(0.25,-0.835) B7(-0.25,-0.835) B8(-0.75,-0.835) B9(-1.25,-0.835) B10(-1.75,-0.835)
  round 1.1 hole 0.7: S1(-2.4,2.15) S2(-2.4,-2.15) S3(2.4,-2.15) S4(2.4,2.15)
  Top Side keep-out region: 0.8,1.8 -0.8,1.8 -0.8,2.5 0.8,2.5
  Top Side keep-out region: 0.8,-2.5 -0.8,-2.5 -0.8,-1.8 0.8,-1.8
  body extent -4.47,-2.3 4.47,2.3, height 9.25
INDM1335X1260X500L275X470N [mm] "Inductor, Molded Body; 12.60 mm L X 12.60 mm W X 5.00 mm H body"
  rrect12% 4.288x5.01 smd: 1(-5.458,0) 2(5.458,0)
  body extent -7,-6.5 7,6.5, height 5
LEDSC80X160X90L45N_GREEN [mm] "LED, Side Concave Package; 2 pin, 0.80 mm L X 1.60 mm W X 0.90 mm H body, green"
  rrect50% 0.94x0.749 smd: 1(-0.745,0) 2(0.745,0)
  body extent -0.85,-0.45 0.85,0.45, height 0.9
LEDSC80X160X90L45N_RED [mm] "LED, Side Concave Package; 2 pin, 0.80 mm L X 1.60 mm W X 0.90 mm H body, red"
  rrect50% 0.94x0.749 smd: 1(-0.745,0) 2(0.745,0)
  body extent -0.85,-0.45 0.85,0.45, height 0.9
MOLEX_39281023 [mm] "Header, Vertical Shrouded, 4.20 mm row X 5.50 mm column pitch; 1.00 mm lead width, 2 pins, 2 rows, 1 pin per row, 5.40 mm L X 9.60 mm W X 13.10 mm H body"
  rrect50% 2.33x2.33 hole 1.4 paste-2539.97: 1(0,2.75)
  round 2.33 hole 1.4 paste-2539.97: 2(0,-2.75)
  body extent -3.1,-6 3.1,5, height 12.81
MOLEX_428192214 [mm] "10.00mm Pitch Mini-Fit Sr. Header, Single Row, Vertical, 1.57mm PCB Thickness, 2 Circuits"
  round 4 hole 3: 0(-10.73,-3.95) 0(10.73,-3.95)
  round 4 hole 2.8: 1(5,-4.4) 1(5,0) 2(-5,-4.4) 2(-5,0)
  body extent -11.91,-9.46 11.91,4.64, height 21.01
MOLEX_428193214 [mm] "10.00mm Pitch Mini-Fit Sr. Header, Single Row, Vertical, 1.57mm PCB Thickness, 3 Circuits"
  round 4 hole 3: 0(-15.73,-3.95) 0(15.73,-3.95)
  round 4 hole 2.8: 1(10,0) 1(10,-4.4) 2(0,0) 2(0,-4.4) 3(-10,0) 3(-10,-4.4)
  body extent -16.91,-9.45 16.91,4.65, height 21.01
MOLEX_1720650204 [mm] "Mega-Fit Slim Vertical Header, Through Hole, 5.70mm Pitch, Dual Row, 4 Circuits, Black"
  round 0 hole 1.8 unplated mask+0.15: 0(-5.33,5.62)
  rrect50% 3.23x3.23 hole 1.8 paste-2539.97: 1(2.85,-2.85)
  round 3.23 hole 1.8 paste-2539.97: 2(-2.85,-2.85) 3(2.85,2.85) 4(-2.85,2.85)
  body extent -6.02,-6.16 6.03,7.87, height 15.61
MOLEX_5025840460 [mm] "Header, 1.5mm pitch, 4 position, top entry, SMT"
  rrect50% 1.8x3.3 smd: 0(-4.85,1.275) 0(4.85,1.275)
  rrect50% 0.8x2.4 smd: 1(-2.25,-3.775) 2(-0.75,-3.775) 3(0.75,-3.775) 4(2.25,-3.775)
  Top Side keep-out region: 1.9,1.379 3.9,1.379 3.9,3.429 1.9,3.429
  Top Side keep-out region: 5.55,-1.424 2.725,-1.424 2.725,-4.024 5.55,-4.024
  Top Side keep-out region: 1.225,-4.024 1.775,-4.024 1.775,-1.424 1.225,-1.424
  Top Side keep-out region: -0.275,-4.024 0.275,-4.024 0.275,-1.424 -0.275,-1.424
  Top Side keep-out region: -1.775,-4.024 -1.225,-4.024 -1.225,-1.424 -1.775,-1.424
  Top Side keep-out region: -1.9,3.429 -3.9,3.429 -3.9,1.379 -1.9,1.379
  Top Side keep-out region: -0.91,0.869 0.91,0.869 0.91,3.429 -0.91,3.429
  Top Side keep-out region: -5.55,-4.024 -2.725,-4.024 -2.725,-1.424 -5.55,-1.424
  Top Side keep-out lines w0.05: 2.7,-1.449 -2.7,-1.449
  body extent -5.15,-4.22 5.15,3.18, height 7.3
MOLEX_5025840760 [mm] "Connector, 1.50mm Pitch, Receptacle, Single Row, SMT, Vertical, 7 Circuits"
  rrect50% 1.8x3.3 smd: 0(-7.1,1.275) 0(7.1,1.275)
  rrect50% 0.8x2.4 smd: 1(-4.5,-3.775) 2(-3,-3.775) 3(-1.5,-3.775) 4(0,-3.775) 5(1.5,-3.775) 6(3,-3.775) 7(4.5,-3.775)
  Top Side keep-out region: 4.15,1.379 6.15,1.379 6.15,3.429 4.15,3.429
  Top Side keep-out region: 7.8,-1.424 4.95,-1.424 4.95,-4.024 7.8,-4.024
  Top Side keep-out region: 3.45,-4.024 4.05,-4.024 4.05,-1.424 3.45,-1.424
  Top Side keep-out region: 1.95,-4.024 2.55,-4.024 2.55,-1.424 1.95,-1.424
  Top Side keep-out region: 0.45,-4.024 1.05,-4.024 1.05,-1.424 0.45,-1.424
  Top Side keep-out region: -1.05,-4.024 -0.45,-4.024 -0.45,-1.424 -1.05,-1.424
  Top Side keep-out region: -2.55,-4.024 -1.95,-4.024 -1.95,-1.424 -2.55,-1.424
  Top Side keep-out region: -4.15,3.429 -6.15,3.429 -6.15,1.379 -4.15,1.379
  Top Side keep-out region: -4.05,-4.024 -3.45,-4.024 -3.45,-1.424 -4.05,-1.424
  Top Side keep-out region: -7.8,-4.024 -4.95,-4.024 -4.95,-1.424 -7.8,-1.424
  Top Side keep-out region: -0.91,0.869 0.91,0.869 0.91,3.429 -0.91,3.429
  Top Side keep-out lines w0.05: -4.95,-1.449 4.95,-1.449
  body extent -7.4,-4.22 7.4,3.18, height 7.3
MOLEX_5025840860 [mm] "Connector, 1.50mm Pitch, Receptacle, Single Row, SMT, Vertical, 8 Pins"
  rrect50% 1.8x3.3 smd: 0(-7.85,1.275) 0(7.85,1.275)
  rrect50% 0.8x2.4 smd: 1(-5.25,-3.775) 2(-3.75,-3.775) 3(-2.25,-3.775) 4(-0.75,-3.775) 5(0.75,-3.775) 6(2.25,-3.775) 7(3.75,-3.775) 8(5.25,-3.775)
  Top Side keep-out region: 8.55,-1.424 5.7,-1.424 5.7,-4.024 8.55,-4.024
  Top Side keep-out region: 4.9,1.379 6.9,1.379 6.9,3.429 4.9,3.429
  Top Side keep-out region: 4.2,-4.024 4.8,-4.024 4.8,-1.424 4.2,-1.424
  Top Side keep-out region: 2.7,-4.024 3.3,-4.024 3.3,-1.424 2.7,-1.424
  Top Side keep-out region: 1.2,-4.024 1.8,-4.024 1.8,-1.424 1.2,-1.424
  Top Side keep-out region: -0.3,-4.024 0.3,-4.024 0.3,-1.424 -0.3,-1.424
  Top Side keep-out region: -1.8,-4.024 -1.2,-4.024 -1.2,-1.424 -1.8,-1.424
  Top Side keep-out region: -3.3,-4.024 -2.7,-4.024 -2.7,-1.424 -3.3,-1.424
  Top Side keep-out region: -8.55,-4.024 -5.7,-4.024 -5.7,-1.424 -8.55,-1.424
  Top Side keep-out region: -4.8,-4.024 -4.2,-4.024 -4.2,-1.424 -4.8,-1.424
  Top Side keep-out region: -4.9,3.429 -6.9,3.429 -6.9,1.379 -4.9,1.379
  Top Side keep-out region: -0.91,0.869 0.91,0.869 0.91,3.429 -0.91,3.429
  Top Side keep-out lines w0.05: -5.7,-1.449 5.7,-1.449
  body extent -8.15,-4.22 8.15,3.18, height 7.3
"MOLEX_ 430450212" [mm] "Micro-Fit 3.0 Vertical Header, 3.00mm Pitch, Dual Row, 2 Circuits, with PCB Polarizing Peg, Black"
  round 0 hole 1.1 unplated mask+0.15: 0(-3,2.44) 0(3,2.44)
  rrect50% 1.8x1.8 hole 1.1: 1(0,-1.5)
  round 1.8 hole 1.1: 2(0,1.5)
  body extent -3.57,-3.94 3.57,4.83, height 9.95
"MOLEX_ 430450612" [mm] "Micro-Fit 3.0 Vertical Header, 3.00mm Pitch, Dual Row, 6 Circuits, with PCB Polarizing Peg, Black"
  round 0 hole 1.1 unplated mask+0.15: 0(-6,2.44) 0(6,2.44)
  rrect50% 1.8x1.8 hole 1.1: 1(3,-1.5)
  round 1.8 hole 1.1: 2(0,-1.5) 3(-3,-1.5) 4(3,1.5) 5(0,1.5) 6(-3,1.5)
  body extent -6.58,-3.97 6.58,4.8, height 9.95
MTGNPH270A550V8H40 [mm] "Mounting Hole, Non-Plated; 5.50 mm Clearance, 2.70 mm Hole (with 8 vias)"
  round 0 hole 2.7 unplated paste-2539.97 mask+2.75: 1(0,0)
  round 0.6 hole 0.4 paste-2539.97 mask-0.6: 2(0,2.2) 3(-1.56,1.56) 4(-2.2,0) 5(-1.56,-1.56) 6(0,-2.2) 7(1.56,-1.56) 8(2.2,0) 9(1.56,1.56)
  Multi-Layer region: -1.65,0 -2.75,0 -2.739,0.24 -2.708,0.477 -2.656,0.712 -2.584,0.941 -2.492,1.162 -2.382,1.375 -2.253,1.577 -2.107,1.768 -1.944,1.944 -1.768,2.107 -1.577,2.253 -1.375,2.382 -1.162,2.492 -0.941,2.584 -0.712,2.656 -0.477,2.708 -0.24,2.739 0,2.75 0.24,2.739 0.477,2.708 0.712,2.656 0.941,2.584 1.162,2.492 1.375,2.382 1.577,2.253 1.768,2.107 1.944,1.944 2.107,1.768 2.253,1.577 2.382,1.375 2.492,1.162 2.584,0.941 2.656,0.712 2.708,0.477 2.739,0.24 2.75,0 2.739,-0.24 2.708,-0.477 2.656,-0.712 2.584,-0.941 2.492,-1.162 2.382,-1.375 2.253,-1.577 2.107,-1.768 1.944,-1.944 1.768,-2.107 1.577,-2.253 1.375,-2.382 1.162,-2.492 0.941,-2.584 0.712,-2.656 0.477,-2.708 0.24,-2.739 0,-2.75 -0.24,-2.739 -0.477,-2.708 -0.712,-2.656 -0.941,-2.584 -1.162,-2.492 -1.375,-2.382 -1.577,-2.253 -1.768,-2.107 -1.944,-1.944 -2.107,-1.768 -2.253,-1.577 -2.382,-1.375 -2.492,-1.162 -2.584,-0.941 -2.656,-0.712 -2.708,-0.477 -2.739,-0.24 -2.75,0 -1.65,0 -1.644,-0.144 -1.625,-0.286 -1.594,-0.427 -1.55,-0.564 -1.495,-0.697 -1.429,-0.825 -1.352,-0.946 -1.264,-1.061 -1.167,-1.167 -1.061,-1.264 -0.946,-1.352 -0.825,-1.429 -0.697,-1.495 -0.564,-1.55 -0.427,-1.594 -0.286,-1.625 -0.144,-1.644 0,-1.65 0.144,-1.644 0.286,-1.625 0.427,-1.594 0.564,-1.55 0.697,-1.495 0.825,-1.429 0.946,-1.352 1.061,-1.264 1.167,-1.167 1.264,-1.061 1.352,-0.946 1.429,-0.825 1.495,-0.697 1.55,-0.564 1.594,-0.427 1.625,-0.286 1.644,-0.144 1.65,0 1.644,0.144 1.625,0.286 1.594,0.427 1.55,0.564 1.495,0.697 1.429,0.825 1.352,0.946 1.264,1.061 1.167,1.167 1.061,1.264 0.946,1.352 0.825,1.429 0.697,1.495 0.564,1.55 0.427,1.594 0.286,1.625 0.144,1.644 0,1.65 -0.144,1.644 -0.286,1.625 -0.427,1.594 -0.564,1.55 -0.697,1.495 -0.825,1.429 -0.946,1.352 -1.061,1.264 -1.167,1.167 -1.264,1.061 -1.352,0.946 -1.429,0.825 -1.495,0.697 -1.55,0.564 -1.594,0.427 -1.625,0.286 -1.644,0.144 -1.65,0
PANASONIC_AXT410124 [mm] "0.40 mm pitch; 10 pin, 3.90 mm L X 1.45 mm W X 1.24 mm H body"
  rrect50% 0.45x0.5 smd: 0(-1.6,-0.575) 0(-1.6,0.575) 0(1.6,-0.575) 0(1.6,0.575)
  rrect50% 0.2x0.77 smd: 1(-0.8,-1.045) 2(-0.8,1.045) 3(-0.4,-1.045) 4(-0.4,1.045) 5(0,-1.045) 6(0,1.045) 7(0.4,-1.045) 8(0.4,1.045) 9(0.8,-1.045) 10(0.8,1.045)
  Top Side keep-out region: -0.983,0.61 0.983,0.61 0.983,0.335 -0.983,0.335
  Top Side keep-out region: -0.983,-0.335 0.983,-0.335 0.983,-0.61 -0.983,-0.61
  body extent -1.95,-1.17 1.95,1.17, height 1.24
PANASONIC_F_VIB [mil] "Capacitor, Aluminum Electrolytic; F Panasonic Vibration proof 8.30 mm L X 8.30 mm W X 10.50 mm H Body"
  round 1 smd: 1(-137.8,0) 2(137.8,0)
  Top Side region: -206.69,-39.37 -216.72,-36.42 -223.92,-28.86 -226.38,-18.7 -226.38,-18.7 -226.38,18.7 -223.92,28.86 -216.72,36.42 -206.69,39.37 -206.69,39.37 -143.7,39.37 -143.7,79.72 -142.73,84.62 -139.95,88.77 -135.8,91.55 -130.91,92.52 -130.91,92.52 -105.32,92.52 -100.42,91.55 -96.27,88.77 -93.49,84.62 -92.52,79.72 -92.52,79.72 -92.52,39.37 -69.88,39.37 -62.12,38.02 -55.47,33.81 -50.94,27.37 -49.21,19.68 -49.21,19.68 -49.21,-19.68 -50.94,-27.37 -55.47,-33.81 -62.12,-38.02 -69.88,-39.37 -69.88,-39.37 -92.52,-39.37 -92.52,-79.72 -93.49,-84.62 -96.27,-88.77 -100.42,-91.55 -105.32,-92.52 -105.32,-92.52 -130.91,-92.52 -135.8,-91.55 -139.95,-88.77 -142.73,-84.62 -143.7,-79.72 -143.7,-79.72 -143.7,-39.37
  Top Side region: 206.69,39.37 214.37,37.65 220.81,33.11 225.03,26.46 226.37,18.7 226.38,18.7 226.38,-18.7 225.03,-26.46 220.81,-33.11 214.37,-37.65 206.69,-39.37 206.69,-39.37 143.7,-39.37 143.7,-79.72 142.72,-84.62 139.95,-88.77 135.8,-91.55 130.9,-92.52 130.9,-92.52 105.31,-92.52 100.42,-91.55 96.26,-88.77 93.49,-84.62 92.52,-79.72 92.52,-79.72 92.52,-39.37 69.88,-39.37 62.12,-38.02 55.47,-33.81 50.93,-27.37 49.21,-19.68 49.21,-19.68 49.21,19.68 50.93,27.37 55.47,33.81 62.12,38.02 69.88,39.37 69.88,39.37 92.52,39.37 92.52,79.72 93.49,84.62 96.26,88.77 100.42,91.55 105.31,92.52 105.31,92.52 130.9,92.52 135.8,91.55 139.95,88.77 142.72,84.62 143.7,79.72 143.7,79.72 143.7,39.37
  body extent -191,-163 191,163, height 413
RESC100X52X40L22N [mm] "Resistor, Chip; 1.00 mm L X 0.525 mm W X 0.40 mm H body"
  rrect51% 0.59x0.62 smd: 1(-0.47,0) 2(0.47,0)
  body extent -0.55,-0.3 0.55,0.3, height 0.4
RESC200X125X84L35N [mm] "Resistor, Chip; 2.00 mm L X 1.25 mm W X 0.84 mm H body"
  rrect50% 0.96x1.47 smd: 1(-0.925,0) 2(0.925,0)
  body extent -1.1,-0.72 1.1,0.72, height 0.84
RESC320X160X90L47N [mm] "Resistor, Chip; 3.20 mm L X 1.60 mm W X 0.90 mm H body"
  rrect43% 1.15x1.82 smd: 1(-1.48,0) 2(1.48,0)
  body extent -1.7,-0.9 1.7,0.9, height 0.9
SAMTEC_ERM8-025-08.0-L-DV [mm] "0.80 mm Edge Rate® Rugged High Speed Terminal"
  round 1.45 hole 1.45 unplated mask+0.1: 0(-11.4,-1.5)
  round 1.45 hole 1.45 unplated mask+0.15: 0(11.4,-1.5)
  rrect50% 0.5x1.1 smd: 1(-9.6,1.9) 2(-9.6,-1.9) 3(-8.8,1.9) 4(-8.8,-1.9) 5(-8,1.9) 6(-8,-1.9) 7(-7.2,1.9) 8(-7.2,-1.9) 9(-6.4,1.9) 10(-6.4,-1.9) 11(-5.6,1.9) 12(-5.6,-1.9) 13(-4.8,1.9) 14(-4.8,-1.9) 15(-4,1.9) 16(-4,-1.9) 17(-3.2,1.9) 18(-3.2,-1.9) 19(-2.4,1.9) 20(-2.4,-1.9) 21(-1.6,1.9) 22(-1.6,-1.9) 23(-0.8,1.9) 24(-0.8,-1.9) 25(0,1.9) 26(0,-1.9) 27(0.8,1.9) 28(0.8,-1.9) 29(1.6,1.9) 30(1.6,-1.9) 31(2.4,1.9) 32(2.4,-1.9) 33(3.2,1.9) 34(3.2,-1.9) 35(4,1.9) 36(4,-1.9) 37(4.8,1.9) 38(4.8,-1.9) 39(5.6,1.9) 40(5.6,-1.9) 41(6.4,1.9) 42(6.4,-1.9) 43(7.2,1.9) 44(7.2,-1.9) 45(8,1.9) 46(8,-1.9) 47(8.8,1.9) 48(8.8,-1.9) 49(9.6,1.9) 50(9.6,-1.9)
  body extent -13,-2.8 13,2.8, height 11.91
SAMTEC_UMPT-06-07.5-L-V-S-W [mm] "2.00 mm mPOWER® Ultramikro-Power-Terminal, 6-polig"
  round 1.4 hole 0.8: 0a(8.85,-1.2) 0a(8.85,0.8) 0b(-8.85,-1.7) 0b(-8.85,0.3)
  rrect50% 1.3x3.5 smd: 1(5,0) 2(3,0) 3(1,0) 4(-1,0) 5(-3,0) 6(-5,0)
  body extent -9.65,-3.8 9.65,3.8, height 10.9
SAMTEC_UMPT-10-07.5-L-V-S-W [mm] "2.00 mm mPOWER® Ultramikro-Power-Terminal, 10-polig"
  round 1.4 hole 0.8: 0a(12.85,-1.2) 0a(12.85,0.8) 0b(-12.85,-1.7) 0b(-12.85,0.3)
  rrect50% 1.3x3.5 smd: 1(9,0) 2(7,0) 3(5,0) 4(3,0) 5(1,0) 6(-1,0) 7(-3,0) 8(-5,0) 9(-7,0) 10(-9,0)
  body extent -13.65,-3.8 13.65,3.8, height 10.8
SODFL359X170X143L65X95N [mm] "Diode, Small Outline Diode Flat Lead (SODFL); 2.70 mm L X 1.70 mm W X 1.43 mm H body"
  rrect42% 1.2x1.21 smd: 1(-1.505,0) 2(1.505,0)
  body extent -1.9,-0.95 1.9,0.95, height 1.43
SOIC8P127_490X599X175L83X41N [mm] "Small Outline IC (SOIC), 1.27 mm pitch; 8 pin, 4.90 mm L X 3.90 mm W X 1.75 mm H body"
  rrect52% 0.66x2.07 smd: 1(-1.905,-2.42) 2(-0.635,-2.42) 3(0.635,-2.42) 4(1.905,-2.42) 5(1.905,2.42) 6(0.635,2.42) 7(-0.635,2.42) 8(-1.905,2.42)
  body extent -2.5,-3.1 2.5,3.1, height 1.75
SOIC16P127_1139X671X151L61X41N [mm] "DIP8-SMD-Small, 1.27 mm pitch; 16 pin, 11.39 mm L X 4.50 mm W X 1.51 mm H Body"
  rrect50% 0.634x1.501 smd: 1(-4.445,-3.007) 2(-3.175,-3.007) 3(-1.905,-3.007) 4(-0.635,-3.007) 5(0.635,-3.007) 6(1.905,-3.007) 7(3.175,-3.007) 8(4.445,-3.007) 9(4.445,3.007) 10(3.175,3.007) 11(1.905,3.007) 12(0.635,3.007) 13(-0.635,3.007) 14(-1.905,3.007) 15(-3.175,3.007) 16(-4.445,3.007)
  body extent -5.69,-3.35 5.7,3.35, height 1.55
SOT23-5P65_210X110L28X20N [mm] "Small Outline Transistor (SOT23), 0.65 mm pitch; 5 pin, 2.025 mm L X 1.25 mm W X 1.10 mm H body"
  rrect49% 0.37x1.04 smd: 1(-0.65,-0.935) 2(0,-0.935) 3(0.65,-0.935) 4(0.65,0.935) 5(-0.65,0.935)
  body extent -1.12,-1.2 1.12,1.2, height 1.1
Steg_400X90_7Hole [mm] "Steg; 4.00 mm L X 0.90 mm W, 7 Hole"
  round 0 hole 0.35 unplated mask+0.15: 0(-1.5,0) 0(-1,0) 0(-0.5,0) 0(0,0) 0(0.5,0) 0(1,0) 0(1.5,0)
  Keep-Out Layer lines w0.05: 1.95,0 ccw(c1.5,0) 1.5,0.45 -1.5,0.45 ccw(c-1.5,0) -1.95,0
TESTPOINT_c120 [mm] "Test Point; 1 pin, 1.20 mm D X 0.00 mm H body"
  round 1.2 smd paste-2: 1(0,0)
  body extent -0.6,-0.6 0.6,0.6, height 0.01
TESTPOINTMEASURE_c50 [mm] "Test Point Measure; 1 pin, 0.50 mm D X 0.00 mm H body"
  round 0.5 smd paste-2: 1(0,0)
  body extent -0.25,-0.25 0.25,0.25, height 0.01

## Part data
C101 C102 C103 C104 C105 C106 C108 C110 C120 C121: library part CMP-000967-5, "Polymer Hybrid Elco 22uF >=80V 20% D=8mm, H=10.5mm", Case="G, D{}8mm, H{}10.5mm", Manufacturer=Panasonic, Max Operating Temperature=105°C, Maximum Working Voltage=80V, Min Operating Temperature=-55°C, Ripple Current=1.55A, Tolerance=20%
C107 C109 C111: library part CMP-001011-3, "470p C0G/NP0/X7R >=100V 20%", Case=0603, Case (Metric)=1608, Dielectric=C0G/NP0/X7R, Manufacturer=X, Max Operating Temperature=125°C, Maximum Working Voltage=100V, Min Operating Temperature=-55°C, Part Number="Ceramic, 0603, 470pF, 20%, >{}100V, C0G/NP0/X7R, @, Soft Termination: N, -55°C to 125°C", Tolerance=20%
C112: library part CMP-001306-1, "100nF X7R >=50V 20%", Case=0402, Case (Metric)=1005, Dielectric=X7R, Manufacturer=X, Max Operating Temperature=125°C, Maximum Working Voltage=50V, Min Operating Temperature=-55°C, Part Number="Ceramic, 0402, 100nF, 20%, >{}50V, X7R, @, Soft Termination: N, -55°C to 125°C", Tolerance=20%
C113 C114 C115: library part CMP-001012-4, "220pF C0G/NP0/X7R >=100V 20%", Case=0603, Case (Metric)=1608, Dielectric=C0G/NP0/X7R, Manufacturer=X, Max Operating Temperature=125°C, Maximum Working Voltage=100V, Min Operating Temperature=-55°C, Part Number="Ceramic, 0603, 220pF, 20%, >{}100V, C0G/NP0/X7R, @, Soft Termination: N, -55°C to 125°C", Tolerance=20%
C116 C122 C123 C124: library part CMP-000709-3, "100nF X7R >=16V 20%", Case=0402, Case (Metric)=1005, Dielectric=X7R, Manufacturer=X, Max Operating Temperature=125°C, Maximum Working Voltage=16V, Min Operating Temperature=-55°C, Part Number="Ceramic, 0402, 100nF, 20%, >{}16V, X7R, @, Soft Termination: N, -55°C to 125°C", Tolerance=20%
C117 C118: library part CMP-000937-4, "10nF X7R >=630V 20%", Case=0805, Case (Metric)=2012, Dielectric=X7R, Dielectric Withstanding Voltage="> 850V 1sec", Manufacturer=Murata, Max Operating Temperature=125°C, Maximum Working Voltage=630V, Min Operating Temperature=-55°C, Tolerance=20%
C119: library part CMP-000703-3, "100nF X7R >=100V 20%", Case=0603, Case (Metric)=1608, Dielectric=X7R, Manufacturer=X, Max Operating Temperature=125°C, Maximum Working Voltage=100V, Min Operating Temperature=-55°C, Part Number="Ceramic, 0603, 100nF, 20%, >{}100V, X7R, @, Soft Termination: N, -55°C to 125°C", Tolerance=20%
D101 D104: library part CMP-001103-4, "Transient Voltage Suppressor Diode, 60V V(RWM), Unidirectional, 400W, 1 Element, DO-214AC", Breakdown Voltage=66.7V, Case=DO-214AC, Clamping Voltage=96.8V, Manufacturer=X, Max Operating Temperature=150°C, Min Operating Temperature=-55°C
D102 D103 D110 D111: library part CMP-000633-9, "Schottky Diode, >=90V, >=1A, SOD-123FL/SOD-123W", Case="Sub SMA; SOD-123FL", Manufacturer="Taiwan Semiconductor", Max Operating Temperature=150°C, Min Operating Temperature=-55°C, Reverse Voltage=90V, RMS Current=1A
D106: library part CMP-001106-5, "Transient Voltage Suppressor Diode, 12V V(RWM), Bidirectional, 100W, 1 Element, SOD-882/DFN1006", Breakdown Voltage=13V, Case="SOD-882; DFN1006", Manufacturer=Diodes, Max Operating Temperature=125°C, Min Operating Temperature=-40°C
D107 D108 D109: library part CMP-000606-13, "Diode Switching, >=70V, >=150mA, SOD882/DFN1006/0402/SOD-923F", Case="SOD882 / DFN1006 / 0402 / SOD-923F", Manufacturer=MCC, Max Operating Temperature=125°C, Min Operating Temperature=-40°C, Reverse Voltage=70V, RMS Current=150mA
